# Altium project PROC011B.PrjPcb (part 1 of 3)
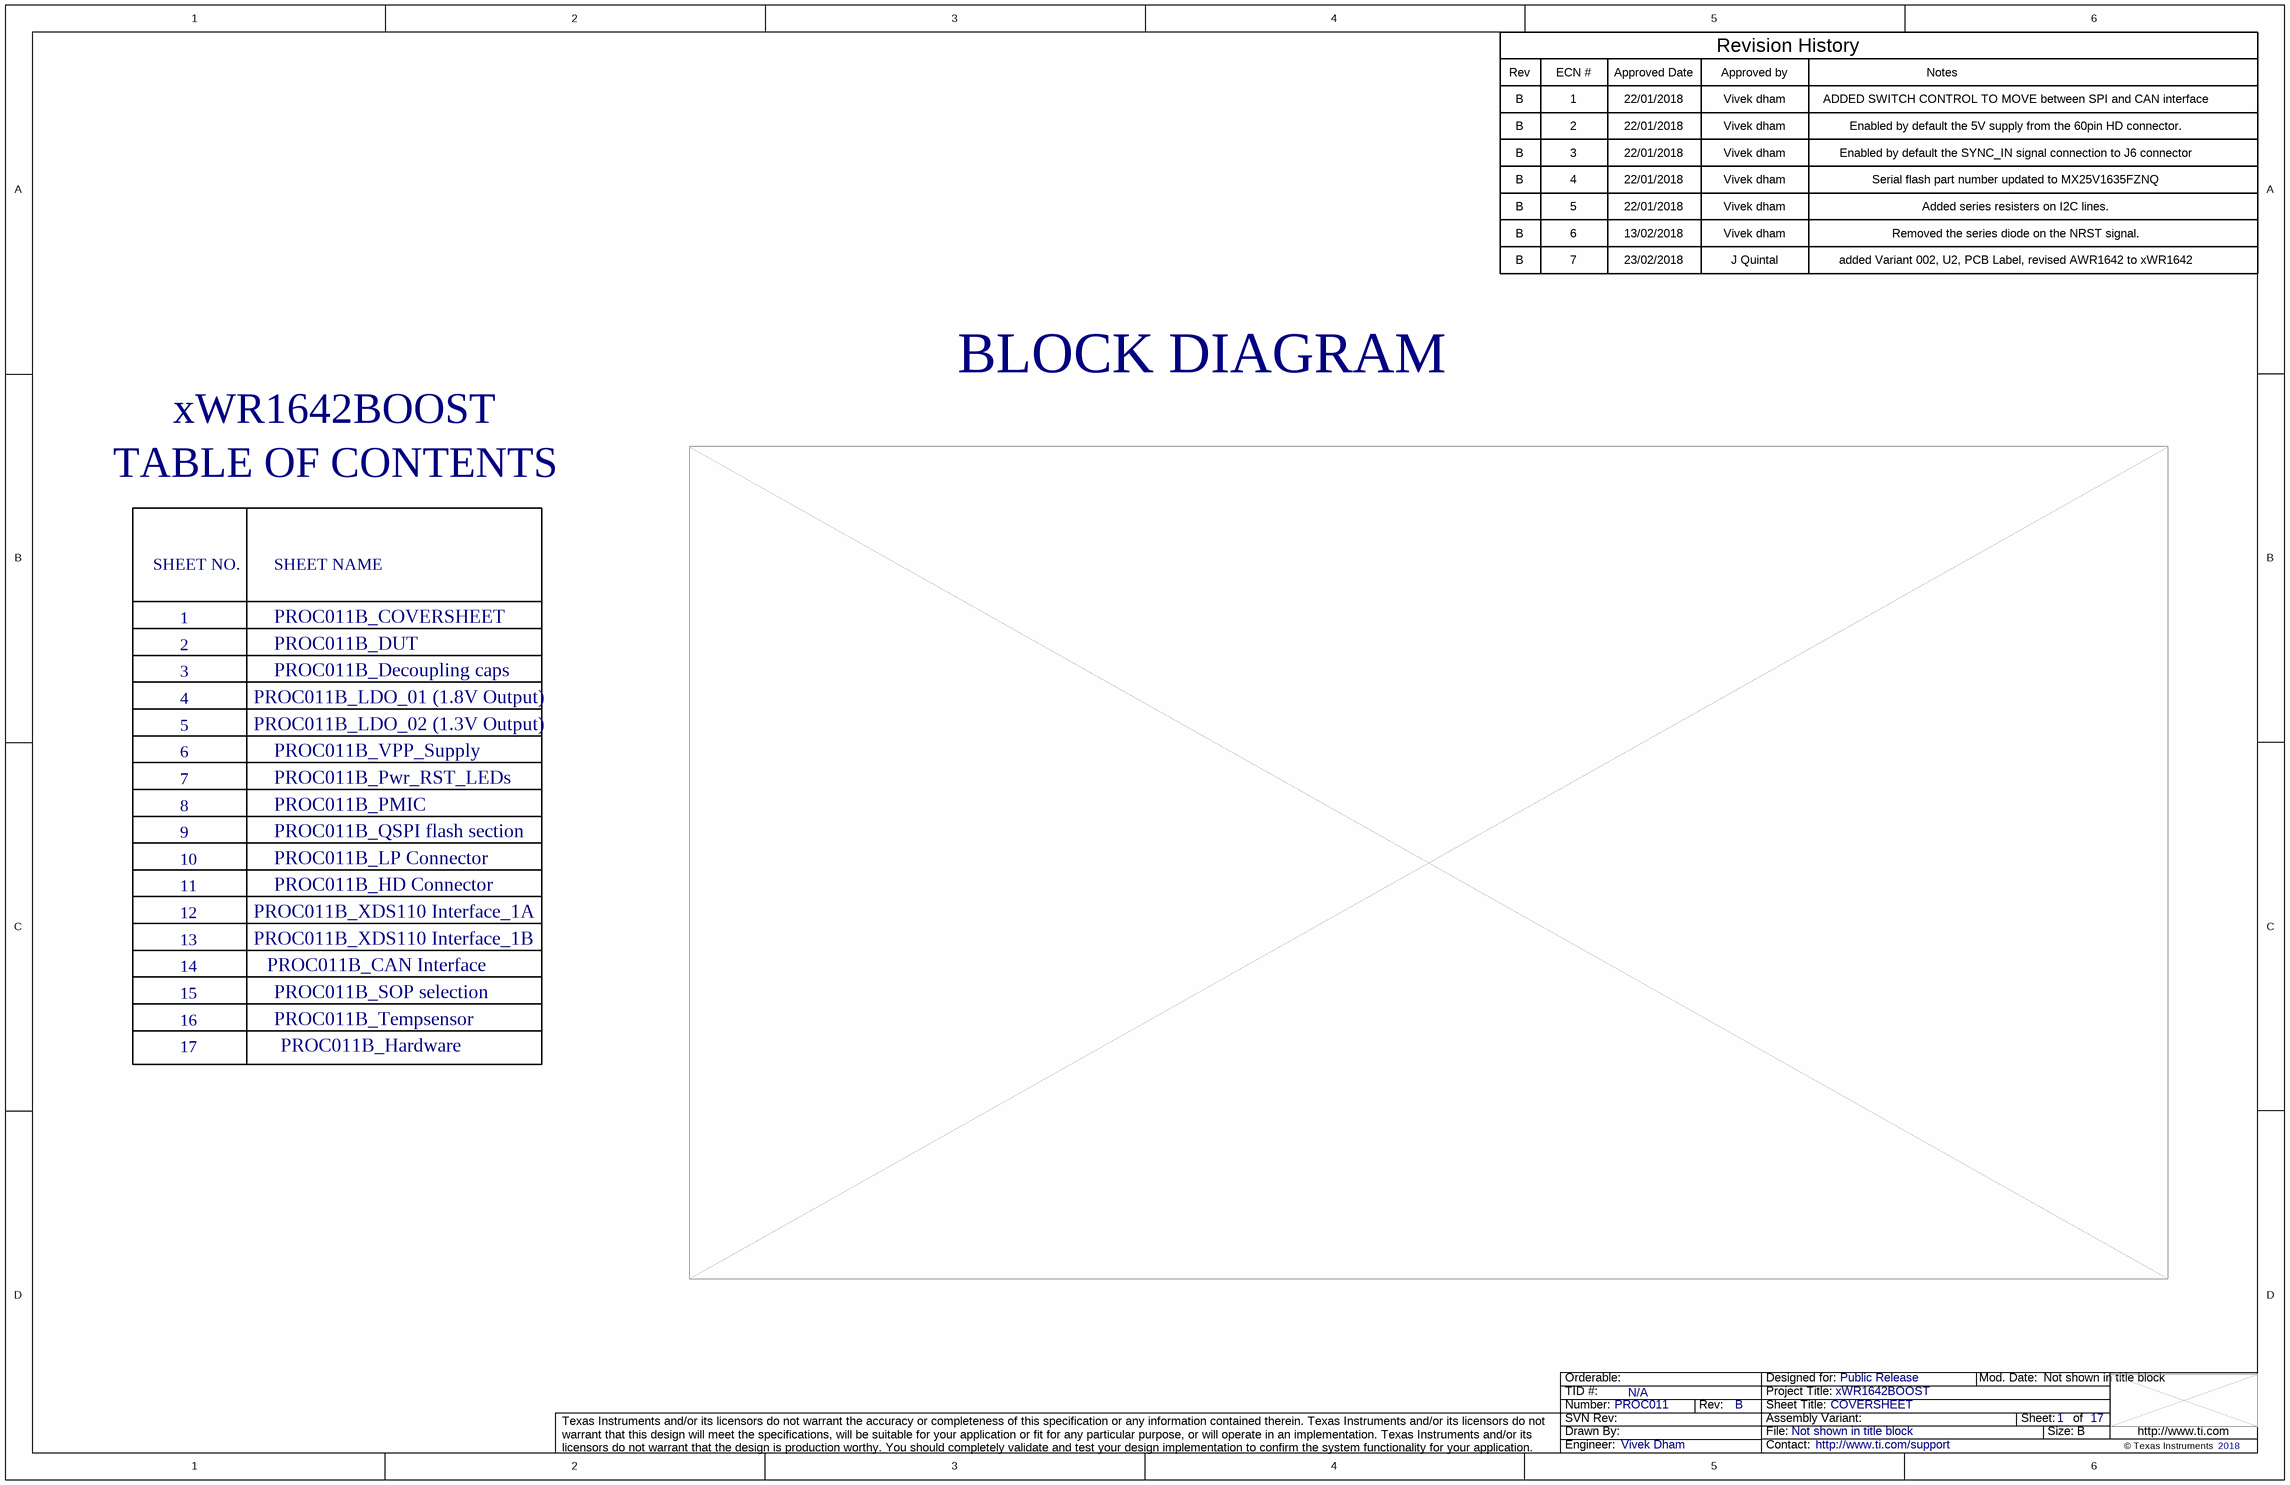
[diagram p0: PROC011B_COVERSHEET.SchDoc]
CopyrightYear: 2018; PCB_Layout: TESSOLVE; PCB_Rev: B; PRJ_Customer: Public Release; PRJ_Engineer: Vivek Dham; PRJ_Number: PROC011; PRJ_Title: xWR1642BOOST; SCH_Rev: B; TechSupport: http://www.ti.com/support; TID: N/A
17 sheets, 399 parts. Net scope: flat (ports and power ports of the same name join across sheets).
Board file: PROC011B_ASCII.PcbDoc
Sheets:
  PROC011B_COVERSHEET.SchDoc
  PROC011B_DUT.SchDoc
  PROC011B_Decoupling caps.SchDoc
  PROC011B_LDO_01 (1.8V Output).SchDoc
  PROC011B_LDO_02 (1.3V Output).SchDoc
  PROC011B_VPP_Supply.SchDoc
  PROC011B_Pwr_RST_LEDs.SchDoc
  PROC011B_PMIC.SchDoc
  PROC011B_QSPI flash section.SchDoc
  PROC011B_LP Connector.SchDoc
  PROC011B_HD Connector.SchDoc
  PROC011B_XDS110 Interface_1A.SchDoc
  PROC011B_XDS110 Interface_1B.SchDoc
  PROC011B_CAN Interface.SchDoc
  PROC011B_SOP selection.SchDoc
  PROC011B_Tempsensor.SchDoc
  PROC011B_Hardware.SchDoc

## Sheet PROC011B_COVERSHEET.SchDoc: COVERSHEET
size 431 x 279 mm; Date: Not shown in title block; ApprovedBy: Not shown in title block; CheckedBy: Not shown in title block; Author: Not shown in title block; CompanyName: Not shown in title block; Engineer: Not shown in title block; Organization: Not shown in title block; Address1: Not shown in title block; Address2: Not shown in title block; Address3: Not shown in title block; Address4: Not shown in title block; DocumentNumber: 1; Revision: Use project parameter SCH_Rev; SheetNumber: 1; SheetTotal: 17; PageSetup: Record=PageOptions¦CenterHorizontal=True¦CenterVertical=True¦PrintScale=0.64¦XCorrection=1.00¦YCorrection=1.00¦PrintKind=0¦BorderSize=5000000¦LeftOffset=0¦BottomOffset=0¦Orientation=2¦PaperLength=1000¦PaperWidth=1000¦Scale=100¦PaperSource=15¦PrintQuality=600¦MediaType=1¦DitherType=10¦PrintScaleMode=1¦PaperKind=Letter

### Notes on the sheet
- Rev
- B
- ECN #
- 1
- Approved Date
- 22/01/2018
- Approved by
- Vivek dham
- Revision History
- Notes
- ADDED SWITCH CONTROL TO MOVE between SPI and CAN interface
- 2
- 3
- Enabled by default the 5V supply from the 60pin HD connector.
- Enabled by default the SYNC_IN signal connection to J6 connector
- 4
- 5
- 6
- 13/02/2018
- Serial flash part number updated to MX25V1635FZNQ
- Added series resisters on I2C lines.
- Removed the series diode on the NRST signal.
- 7
- 23/02/2018
- J Quintal
- added Variant 002, U2, PCB Label, revised AWR1642 to xWR1642
- xWR1642BOOST
- BLOCK DIAGRAM
- TABLE OF CONTENTS
- SHEET NO.
- SHEET NAME
- PROC011B_COVERSHEET
- PROC011B_LDO_01 (1.8V Output)
- PROC011B_DUT
- PROC011B_Decoupling caps
- PROC011B_LDO_02 (1.3V Output)
- PROC011B_VPP_Supply
- 8
- 9
- PROC011B_Pwr_RST_LEDs
- PROC011B_PMIC
- PROC011B_QSPI flash section
- 10
- 11
- PROC011B_LP Connector
- PROC011B_HD Connector
- 12
- 13
- 14
- PROC011B_XDS110 Interface_1A
- PROC011B_XDS110 Interface_1B
- PROC011B_CAN Interface
- 15
- 16
- PROC011B_SOP selection
- PROC011B_Tempsensor
- 17
- PROC011B_Hardware

## Sheet PROC011B_DUT.SchDoc: DUT
size 431 x 279 mm; Date: Not shown in title block; ApprovedBy: Not shown in title block; CheckedBy: Not shown in title block; Author: Not shown in title block; CompanyName: Not shown in title block; Engineer: Not shown in title block; Organization: Not shown in title block; Address1: Not shown in title block; Address2: Not shown in title block; Address3: Not shown in title block; Address4: Not shown in title block; DocumentNumber: 1; Revision: Use project parameter SCH_Rev; SheetNumber: 2; SheetTotal: 17; PageSetup: Record=PageOptions¦CenterHorizontal=True¦CenterVertical=True¦PrintScale=0.64¦XCorrection=1.00¦YCorrection=1.00¦PrintKind=0¦BorderSize=5000000¦LeftOffset=0¦BottomOffset=0¦Orientation=2¦PaperLength=1000¦PaperWidth=1000¦Scale=100¦PaperSource=15¦PrintQuality=600¦MediaType=1¦DitherType=10¦PrintScaleMode=1¦PaperKind=Letter
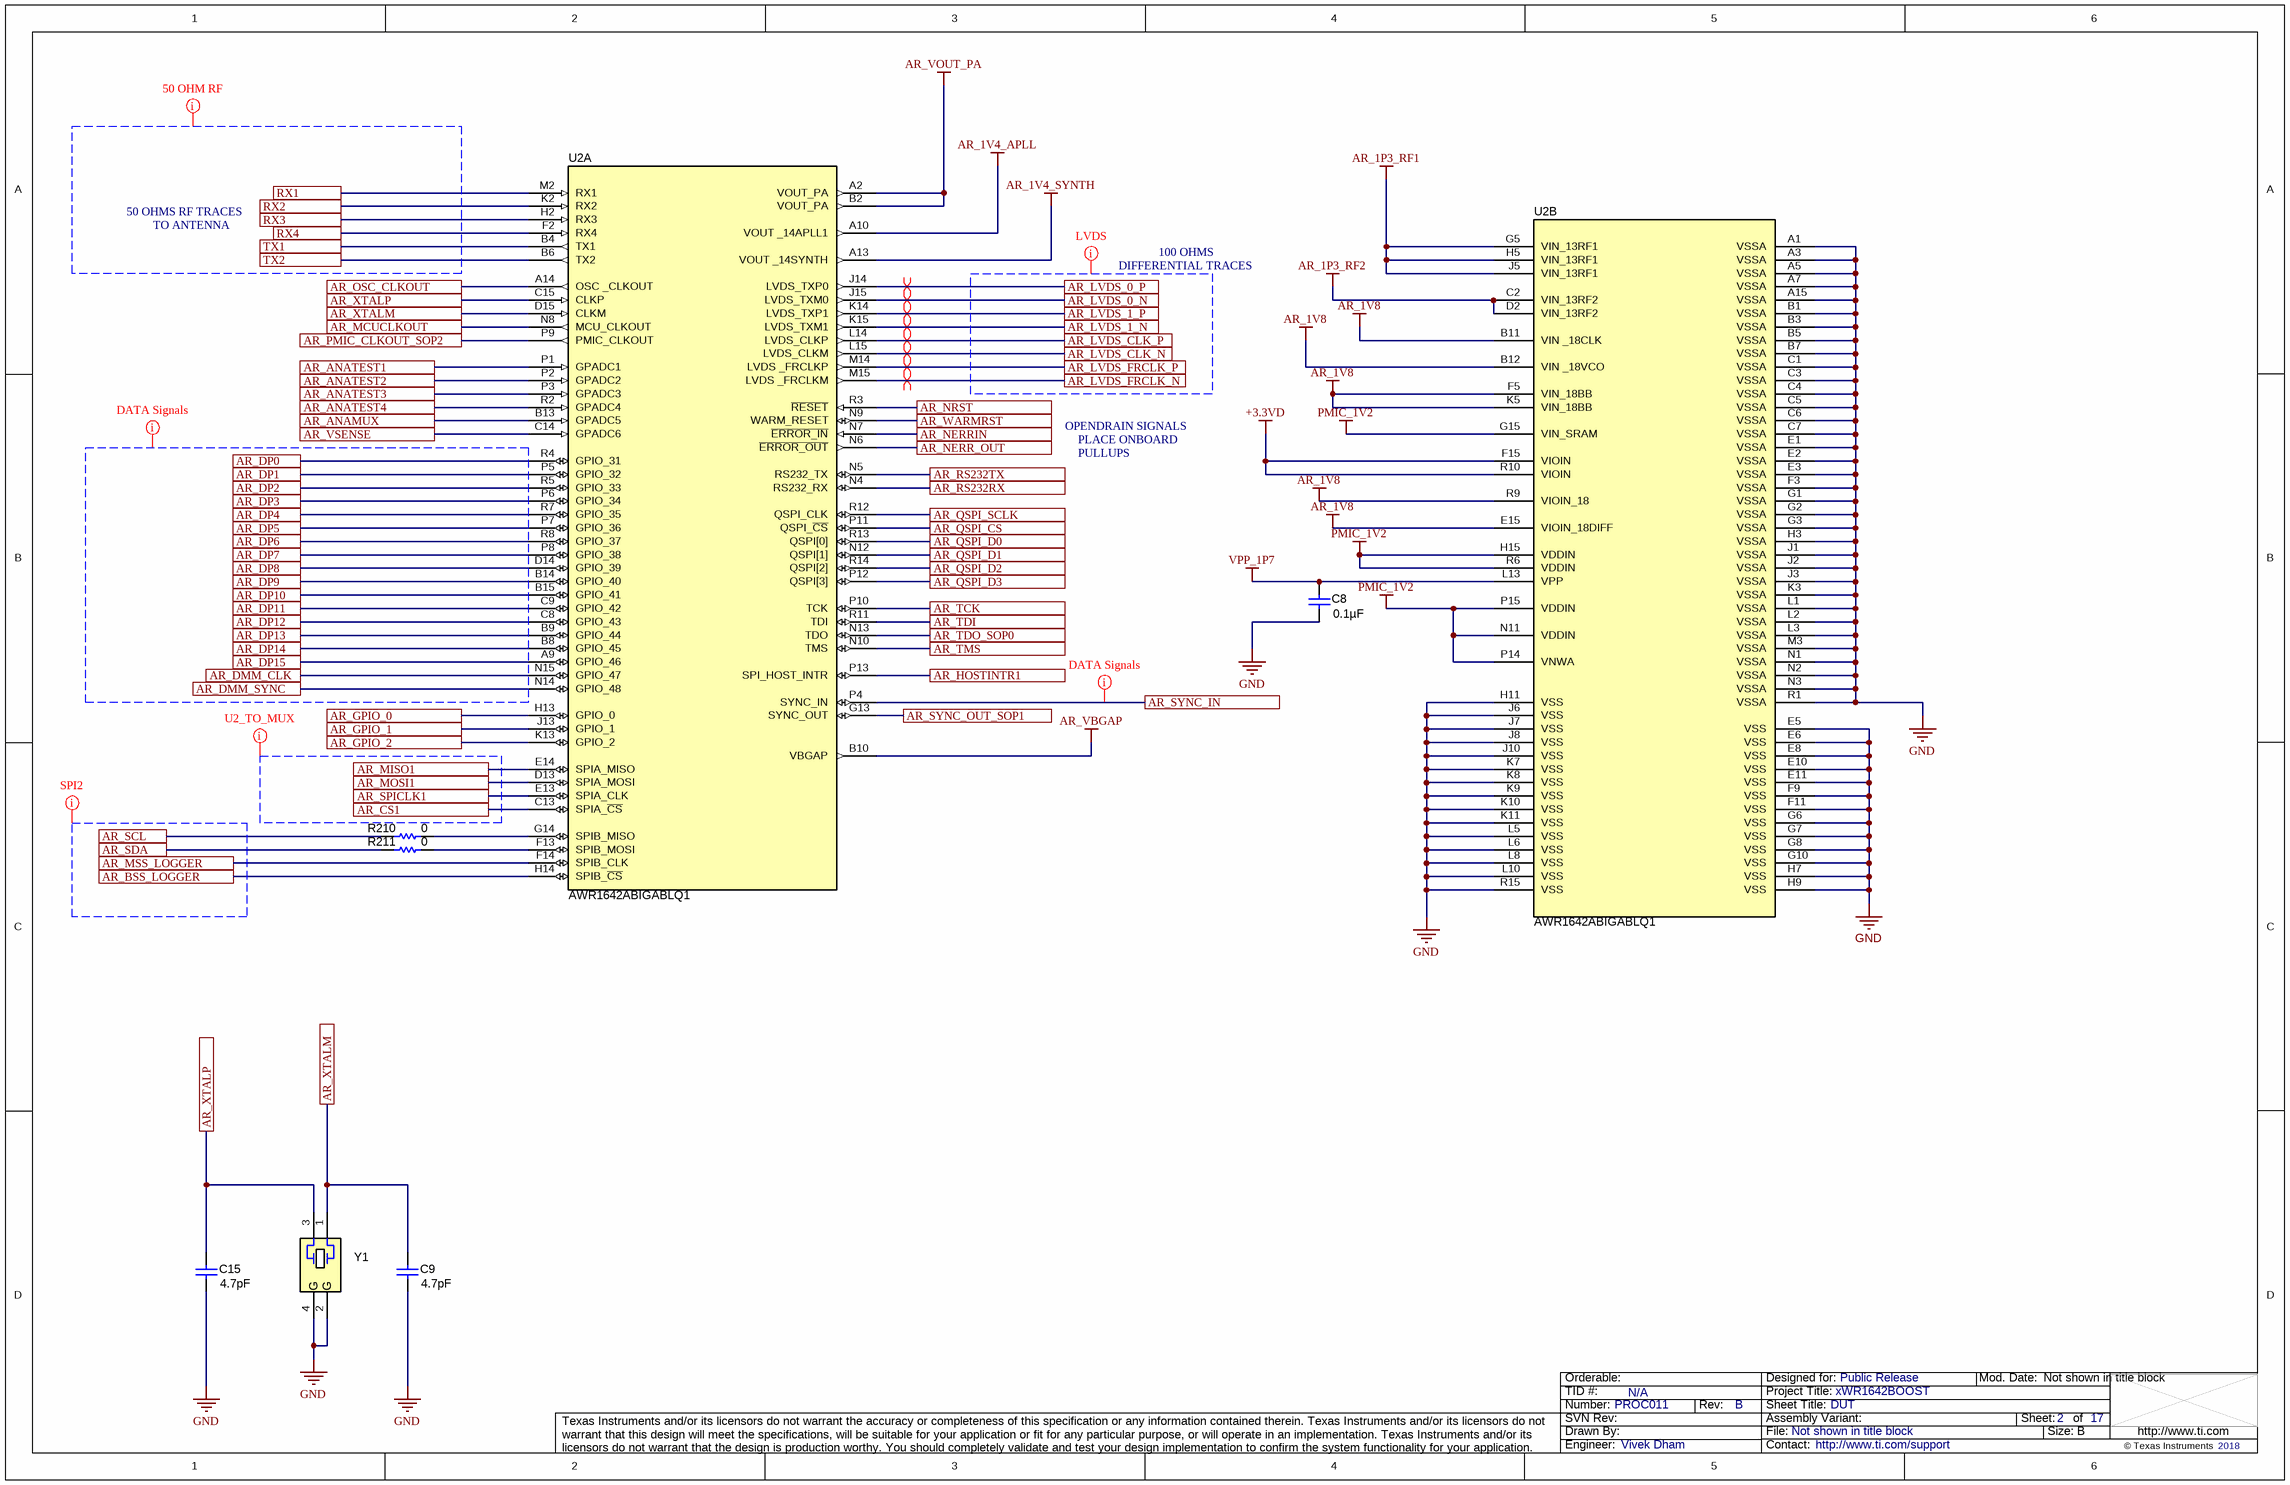
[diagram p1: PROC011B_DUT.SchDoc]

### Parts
C8  ValueDisplayed: 0.1µF  [0201_033]  (hidden comment: C0603X7S1A104K030BC)
C9  ValueDisplayed: 4.7pF  [0402L]  (hidden comment: GJM1555C1H4R7BB01D)
C15  ValueDisplayed: 4.7pF  [0402L]  (hidden comment: GJM1555C1H4R7BB01D)
R210  ValueDisplayed: 0  [0201]  (hidden comment: CRCW02010000Z0ED)
R211  ValueDisplayed: 0  [0201]  (hidden comment: CRCW02010000Z0ED)
U2  PartNumber: AWR1642ABIGABLQ1  [ABL0161B]  (hidden comment: X1642BIGABL)  (parts A,B of 2)
Y1  CX3225SA40000D0PTWCC  [Kyocera_CX3225SA]  (value not drawn)

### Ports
AR_ANAMUX, AR_ANATEST1, AR_ANATEST2, AR_ANATEST3, AR_ANATEST4, AR_BSS_LOGGER, AR_CS1, AR_DMM_CLK, AR_DMM_SYNC, AR_DP0, AR_DP1, AR_DP2, AR_DP3, AR_DP4, AR_DP5, AR_DP6, AR_DP7, AR_DP8, AR_DP9, AR_DP10, AR_DP11, AR_DP12, AR_DP13, AR_DP14, AR_DP15, AR_GPIO_0, AR_GPIO_1, AR_GPIO_2, AR_HOSTINTR1, AR_LVDS_0_N, AR_LVDS_0_P, AR_LVDS_1_N, AR_LVDS_1_P, AR_LVDS_CLK_N, AR_LVDS_CLK_P, AR_LVDS_FRCLK_N, AR_LVDS_FRCLK_P, AR_MCUCLKOUT, AR_MISO1, AR_MOSI1, AR_MSS_LOGGER, AR_NERR_OUT, AR_NERRIN, AR_NRST, AR_OSC_CLKOUT, AR_PMIC_CLKOUT_SOP2, AR_QSPI_CS, AR_QSPI_D0, AR_QSPI_D1, AR_QSPI_D2, AR_QSPI_D3, AR_QSPI_SCLK, AR_RS232RX, AR_RS232TX, AR_SCL, AR_SDA, AR_SPICLK1, AR_SYNC_IN, AR_SYNC_OUT_SOP1, AR_TCK, AR_TDI, AR_TDO_SOP0, AR_TMS, AR_VSENSE, AR_WARMRST, AR_XTALM, AR_XTALP, RX1, RX2, RX3, RX4, TX1, TX2

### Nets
+3.3VD: U2.F15(VIOIN) U2.R10(VIOIN)
AR_1P3_RF1: U2.G5(VIN_13RF1) U2.H5(VIN_13RF1) U2.J5(VIN_13RF1)
AR_1P3_RF2: U2.C2(VIN_13RF2) U2.D2(VIN_13RF2)
AR_1V4_APLL: U2.A10(VOUT__14APLL1)
AR_1V4_SYNTH: U2.A13(VOUT__14SYNTH)
AR_1V8: U2.B11(VIN__18CLK) U2.B12(VIN__18VCO) U2.E15(VIOIN_18DIFF) U2.F5(VIN_18BB) U2.K5(VIN_18BB) U2.R9(VIOIN_18)
AR_VBGAP: U2.B10(VBGAP)
AR_VOUT_PA: U2.A2(VOUT_PA) U2.B2(VOUT_PA)
GND: C8.1 C9.1 C15.1 U2.A1(VSSA) U2.A3(VSSA) U2.A5(VSSA) U2.A7(VSSA) U2.A15(VSSA) U2.B1(VSSA) U2.B3(VSSA) U2.B5(VSSA) U2.B7(VSSA) U2.C1(VSSA) U2.C3(VSSA) U2.C4(VSSA) U2.C5(VSSA) U2.C6(VSSA) U2.C7(VSSA) U2.E1(VSSA) U2.E2(VSSA) U2.E3(VSSA) U2.E5(VSS) U2.E6(VSS) U2.E8(VSS) U2.E10(VSS) U2.E11(VSS) U2.F3(VSSA) U2.F9(VSS) U2.F11(VSS) U2.G1(VSSA) U2.G2(VSSA) U2.G3(VSSA) U2.G6(VSS) U2.G7(VSS) U2.G8(VSS) U2.G10(VSS) U2.H3(VSSA) U2.H7(VSS) U2.H9(VSS) U2.H11(VSS) U2.J1(VSSA) U2.J2(VSSA) U2.J3(VSSA) U2.J6(VSS) U2.J7(VSS) U2.J8(VSS) U2.J10(VSS) U2.K3(VSSA) U2.K7(VSS) U2.K8(VSS) U2.K9(VSS) U2.K10(VSS) U2.K11(VSS) U2.L1(VSSA) U2.L2(VSSA) U2.L3(VSSA) U2.L5(VSS) U2.L6(VSS) U2.L8(VSS) U2.L10(VSS) U2.M3(VSSA) U2.N1(VSSA) U2.N2(VSSA) U2.N3(VSSA) U2.R1(VSSA) U2.R15(VSS) Y1.2(GND) Y1.4(GND)
PMIC_1V2: U2.G15(VIN_SRAM) U2.H15(VDDIN) U2.N11(VDDIN) U2.P14(VNWA) U2.P15(VDDIN) U2.R6(VDDIN)
VPP_1P7: C8.2 U2.L13(VPP)
AR_ANAMUX: U2.B13(GPADC5) ; port AR_ANAMUX
AR_ANATEST1: U2.P1(GPADC1) ; port AR_ANATEST1
AR_ANATEST2: U2.P2(GPADC2) ; port AR_ANATEST2
AR_ANATEST3: U2.P3(GPADC3) ; port AR_ANATEST3
AR_ANATEST4: U2.R2(GPADC4) ; port AR_ANATEST4
AR_BSS_LOGGER: U2.H14(SPIB_~{CS}) ; port AR_BSS_LOGGER
AR_CS1: U2.C13(SPIA_~{CS}) ; port AR_CS1
AR_DMM_CLK: U2.N15(GPIO_47) ; port AR_DMM_CLK
AR_DMM_SYNC: U2.N14(GPIO_48) ; port AR_DMM_SYNC
AR_DP0: U2.R4(GPIO_31) ; port AR_DP0
AR_DP1: U2.P5(GPIO_32) ; port AR_DP1
AR_DP2: U2.R5(GPIO_33) ; port AR_DP2
AR_DP3: U2.P6(GPIO_34) ; port AR_DP3
AR_DP4: U2.R7(GPIO_35) ; port AR_DP4
AR_DP5: U2.P7(GPIO_36) ; port AR_DP5
AR_DP6: U2.R8(GPIO_37) ; port AR_DP6
AR_DP7: U2.P8(GPIO_38) ; port AR_DP7
AR_DP8: U2.D14(GPIO_39) ; port AR_DP8
AR_DP9: U2.B14(GPIO_40) ; port AR_DP9
AR_DP10: U2.B15(GPIO_41) ; port AR_DP10
AR_DP11: U2.C9(GPIO_42) ; port AR_DP11
AR_DP12: U2.C8(GPIO_43) ; port AR_DP12
AR_DP13: U2.B9(GPIO_44) ; port AR_DP13
AR_DP14: U2.B8(GPIO_45) ; port AR_DP14
AR_DP15: U2.A9(GPIO_46) ; port AR_DP15
AR_GPIO_0: U2.H13(GPIO_0) ; port AR_GPIO_0
AR_GPIO_1: U2.J13(GPIO_1) ; port AR_GPIO_1
AR_GPIO_2: U2.K13(GPIO_2) ; port AR_GPIO_2
AR_HOSTINTR1: U2.P13(SPI_HOST_INTR) ; port AR_HOSTINTR1
AR_LVDS_0_N: U2.J15(LVDS_TXM0) ; port AR_LVDS_0_N
AR_LVDS_0_P: U2.J14(LVDS_TXP0) ; port AR_LVDS_0_P
AR_LVDS_1_N: U2.K15(LVDS_TXM1) ; port AR_LVDS_1_N
AR_LVDS_1_P: U2.K14(LVDS_TXP1) ; port AR_LVDS_1_P
AR_LVDS_CLK_N: U2.L15(LVDS_CLKM) ; port AR_LVDS_CLK_N
AR_LVDS_CLK_P: U2.L14(LVDS_CLKP) ; port AR_LVDS_CLK_P
AR_LVDS_FRCLK_N: U2.M15(LVDS__FRCLKM) ; port AR_LVDS_FRCLK_N
AR_LVDS_FRCLK_P: U2.M14(LVDS__FRCLKP) ; port AR_LVDS_FRCLK_P
AR_MCUCLKOUT: U2.N8(MCU_CLKOUT) ; port AR_MCUCLKOUT
AR_MISO1: U2.E14(SPIA_MISO) ; port AR_MISO1
AR_MOSI1: U2.D13(SPIA_MOSI) ; port AR_MOSI1
AR_MSS_LOGGER: U2.F14(SPIB_CLK) ; port AR_MSS_LOGGER
AR_NERR_OUT: U2.N6(~{ERROR_OUT}) ; port AR_NERR_OUT
AR_NERRIN: U2.N7(~{ERROR_IN}) ; port AR_NERRIN
AR_NRST: U2.R3(~{RESET}) ; port AR_NRST
AR_OSC_CLKOUT: U2.A14(OSC__CLKOUT) ; port AR_OSC_CLKOUT
AR_PMIC_CLKOUT_SOP2: U2.P9(PMIC_CLKOUT) ; port AR_PMIC_CLKOUT_SOP2
AR_QSPI_CS: U2.P11(QSPI_~{CS}) ; port AR_QSPI_CS
AR_QSPI_D0: U2.R13(QSPI[0]) ; port AR_QSPI_D0
AR_QSPI_D1: U2.N12(QSPI[1]) ; port AR_QSPI_D1
AR_QSPI_D2: U2.R14(QSPI[2]) ; port AR_QSPI_D2
AR_QSPI_D3: U2.P12(QSPI[3]) ; port AR_QSPI_D3
AR_QSPI_SCLK: U2.R12(QSPI_CLK) ; port AR_QSPI_SCLK
AR_RS232RX: U2.N4(RS232_RX) ; port AR_RS232RX
AR_RS232TX: U2.N5(RS232_TX) ; port AR_RS232TX
AR_SCL: R210.1 ; port AR_SCL
AR_SDA: R211.1 ; port AR_SDA
AR_SPICLK1: U2.E13(SPIA_CLK) ; port AR_SPICLK1
AR_SYNC_IN: U2.P4(SYNC_IN) ; port AR_SYNC_IN
AR_SYNC_OUT_SOP1: U2.G13(SYNC_OUT) ; port AR_SYNC_OUT_SOP1
AR_TCK: U2.P10(TCK) ; port AR_TCK
AR_TDI: U2.R11(TDI) ; port AR_TDI
AR_TDO_SOP0: U2.N13(TDO) ; port AR_TDO_SOP0
AR_TMS: U2.N10(TMS) ; port AR_TMS
AR_VSENSE: U2.C14(GPADC6) ; port AR_VSENSE
AR_WARMRST: U2.N9(WARM_RESET) ; port AR_WARMRST
AR_XTALM: C9.2 U2.D15(CLKM) Y1.1 ; port AR_XTALM
AR_XTALP: C15.2 U2.C15(CLKP) Y1.3 ; port AR_XTALP
RX1: U2.M2(RX1) ; port RX1
RX2: U2.K2(RX2) ; port RX2
RX3: U2.H2(RX3) ; port RX3
RX4: U2.F2(RX4) ; port RX4
TX1: U2.B4(TX1) ; port TX1
TX2: U2.B6(TX2) ; port TX2
NetR210_2: R210.2 U2.G14(SPIB_MISO)
NetR211_2: R211.2 U2.F13(SPIB_MOSI)

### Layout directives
differential pair: AR_LVDS_0_N, AR_LVDS_0_P, AR_LVDS_1_N, AR_LVDS_1_P, AR_LVDS_CLK_N, AR_LVDS_CLK_P, AR_LVDS_FRCLK_N, AR_LVDS_FRCLK_P
net class LVDS: (no net found under the mark)
net class DATA0-15: (no net found under the mark), AR_SYNC_IN
net class RF_RX&TX: (no net found under the mark)
net class SPI2: (no net found under the mark)
net class U2_TO_MUX: (no net found under the mark)

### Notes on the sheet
- 50 OHMS RF TRACES
- TO ANTENNA
- DIFFERENTIAL TRACES
- 100 OHMS
- OPENDRAIN SIGNALS
- PLACE ONBOARD
- PULLUPS

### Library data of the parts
C8 = CMP-0078219-1: CAP, CERM, 0.1 µF, 10 V,+/- 10%, X7S, 0201; Manufacturer: TDK; TaMin_C: -55°C; Polarized: N; Green_Lifecycle: NRND; SizeAreaWB_mm2: 2.08; Green_REACh: Passed; U/M: EA; Value: 0.1uF; TaMax_C: 125°C; SizeZ_mm: 0.33; SizeX_mm: 0.6; SizeY_mm: 0.3; Cap_Case: 0201; Value2: 10V; SizeArea_mm2: 0.18; CompType: Capacitor; Cap_F: 100nF; AEC Category: Q200
C9 C15 = CMP-0006367-2: CAP, CERM, 4.7 pF, 50 V, +/- 2%, C0G/NP0, 0402; Manufacturer: MuRata; TaMin_C: -55°C; Polarized: N; SizeAreaWB_mm2: 3; Value1: Unknown; U/M: EA; Value: 4.7pF; TaMax_C: 125°C; SizeZ_mm: 0.6; SizeX_mm: 1; SizeY_mm: 0.5; Cap_Case: 0402; Value2: 50V; CompType: Capacitor; AEC Category: Q200
R210 R211 = CMP-0027008-4: RES, 0, 5%, 0.05 W, 0201; Manufacturer: Vishay-Dale; Power_W: 50mW; TempCo: ppm/C; Value_Code: 0000; Value: 0; EIA_Code: E24; SizeX_mm: 0.6; SizeY_mm: 0.3; SizeZ_mm: 0.26; Value2: 0.05W; SizeArea_mm2: 0.18; CompType: Resistor; AEC Qualified: N; AEC Category: Q200; INSTALL: DNP
U2 = CMP-0077311-2: Single-Chip 77- and 79-GHz FMCW Radar Sensor, ABL0161B (FCBGA-161); Manufacturer: Texas Instruments; SizeX_mm: 10.4; CompType: IC; SizeZ_mm: 1.17; SizeArea_mm2: 108.16; SizeAreaWB_mm2: 153.76; U/M: EA
Y1 = CMP-0004694-3: Crystal, 40 MHz, 8pF, SMD; Manufacturer: Kyocera; TaMin_C: -40°C; Frequency Stability: +/-200ppm; SizeAreaWB_mm2: 14.7; Frequency_Fixed: 40MHz; TaMax_C: 125°C; SizeZ_mm: 0.8; SizeX_mm: 2.5; SizeY_mm: 3.2; SizeArea_mm2: 8

## Sheet PROC011B_Decoupling caps.SchDoc: Decoupling caps
size 431 x 279 mm; Date: Not shown in title block; ApprovedBy: Not shown in title block; CheckedBy: Not shown in title block; Author: Not shown in title block; CompanyName: Not shown in title block; Engineer: Not shown in title block; Organization: Not shown in title block; Address1: Not shown in title block; Address2: Not shown in title block; Address3: Not shown in title block; Address4: Not shown in title block; DocumentNumber: 1; Revision: Use project parameter SCH_Rev; SheetNumber: 3; SheetTotal: 17; PageSetup: Record=PageOptions¦CenterHorizontal=True¦CenterVertical=True¦PrintScale=1.00¦XCorrection=1.00¦YCorrection=1.00¦PrintKind=0¦BorderSize=5000000¦LeftOffset=0¦BottomOffset=0¦Orientation=2¦PaperLength=1000¦PaperWidth=1000¦Scale=100¦PaperSource=15¦PrintQuality=600¦MediaType=1¦DitherType=10¦PaperKind=Letter¦PrintScaleMode=1
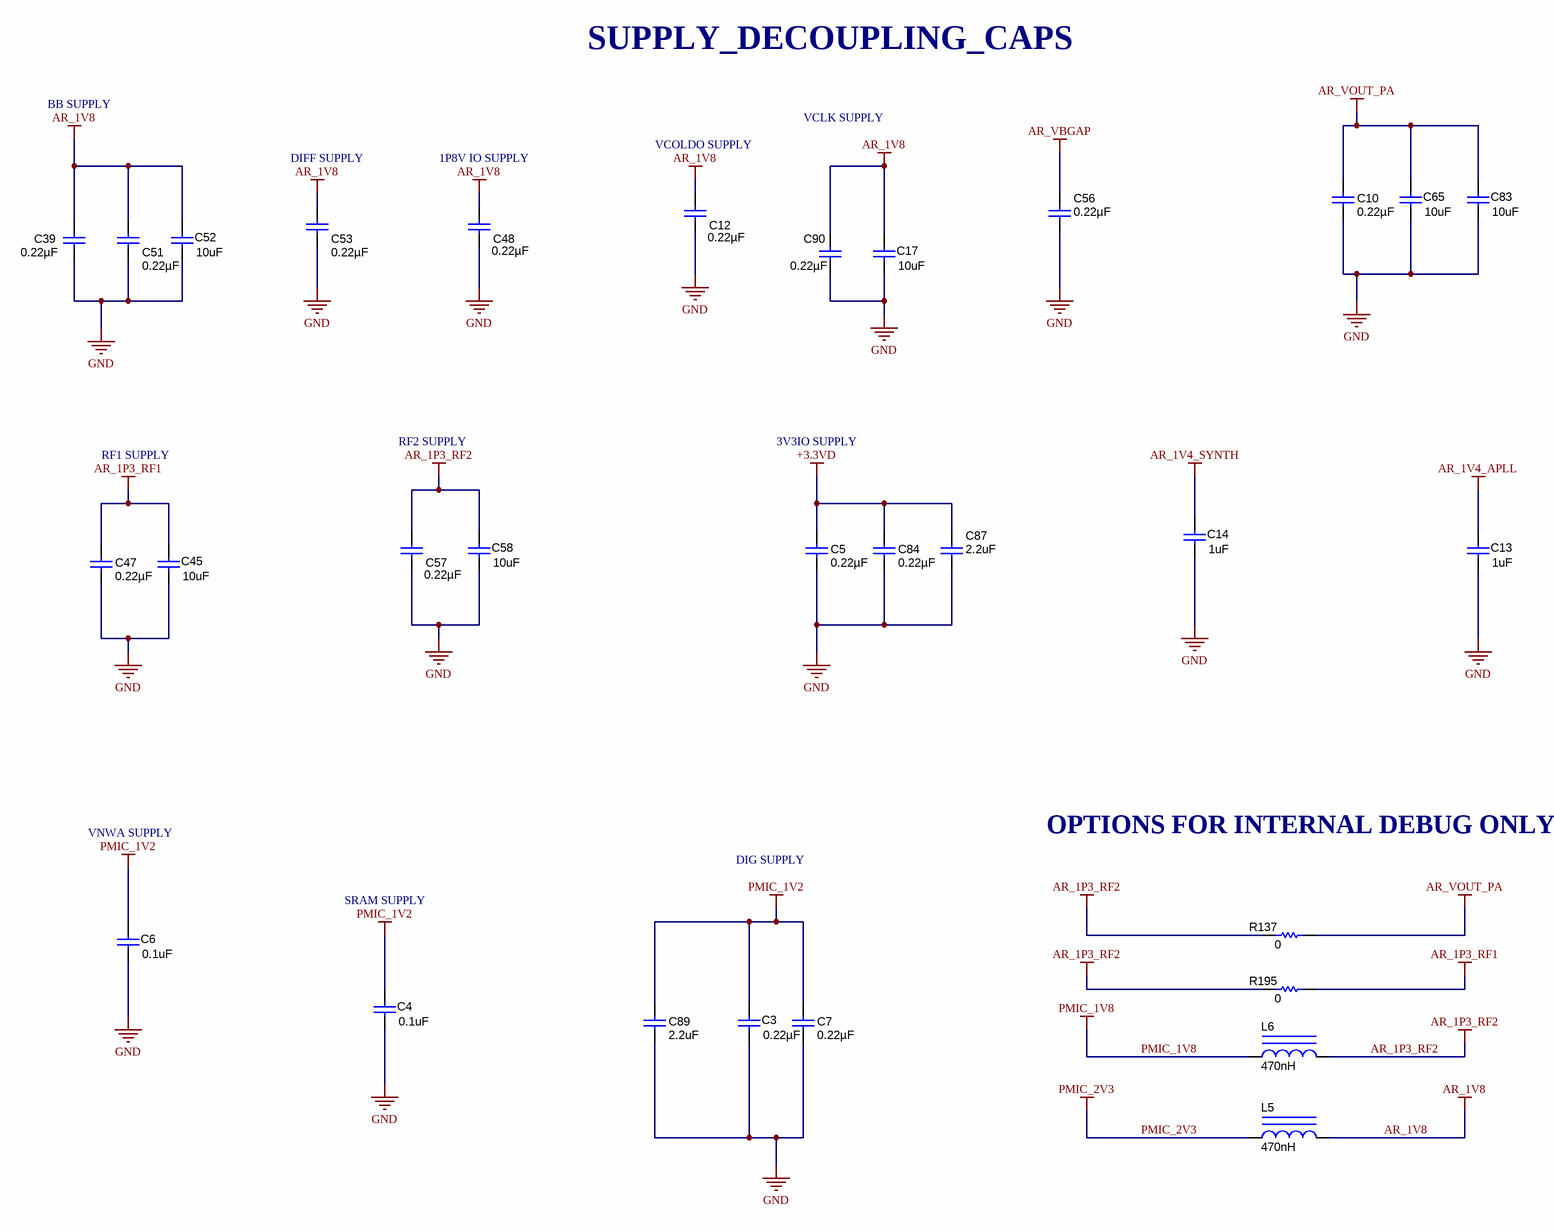
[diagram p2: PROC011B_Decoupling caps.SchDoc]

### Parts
C3  ValueDisplayed: 0.22µF  [0402L]  (hidden comment: GCM155R71C224KE02D)
C4  ValueDisplayed: 0.1uF  [0402L]  (hidden comment: GCM155R71C104KA55D)
C5  ValueDisplayed: 0.22µF  [0402L]  (hidden comment: GCM155R71C224KE02D)
C6  ValueDisplayed: 0.1uF  [0402L]  (hidden comment: GCM155R71C104KA55D)
C7  ValueDisplayed: 0.22µF  [0402L]  (hidden comment: GCM155R71C224KE02D)
C10  ValueDisplayed: 0.22µF  [0402L]  (hidden comment: GCM155R71C224KE02D)
C12  ValueDisplayed: 0.22µF  [0402L]  (hidden comment: GCM155R71C224KE02D)
C13  ValueDisplayed: 1uF  [0603]  (hidden comment: GCM188R71C105KA64D)
C14  ValueDisplayed: 1uF  [0603]  (hidden comment: GCM188R71C105KA64D)
C17  ValueDisplayed: 10uF  [0805_HV]  (hidden comment: GCM21BR71A106KE22L)
C39  ValueDisplayed: 0.22µF  [0402L]  (hidden comment: GCM155R71C224KE02D)
C45  ValueDisplayed: 10uF  [0805_HV]  (hidden comment: GCM21BR71A106KE22L)
C47  ValueDisplayed: 0.22µF  [0402L]  (hidden comment: GCM155R71C224KE02D)
C48  ValueDisplayed: 0.22µF  [0402L]  (hidden comment: GCM155R71C224KE02D)
C51  ValueDisplayed: 0.22µF  [0402L]  (hidden comment: GCM155R71C224KE02D)
C52  ValueDisplayed: 10uF  [0805_HV]  (hidden comment: GCM21BR71A106KE22L)
C53  ValueDisplayed: 0.22µF  [0402L]  (hidden comment: GCM155R71C224KE02D)
C56  ValueDisplayed: 0.22µF  [0402L]  (hidden comment: GCM155R71C224KE02D)
C57  ValueDisplayed: 0.22µF  [0402L]  (hidden comment: GCM155R71C224KE02D)
C58  ValueDisplayed: 10uF  [0805_HV]  (hidden comment: GCM21BR71A106KE22L)
C65  ValueDisplayed: 10uF  [0805_HV]  (hidden comment: GCM21BR71A106KE22L)
C83  ValueDisplayed: 10uF  [0805_HV]  (hidden comment: GCM21BR71A106KE22L)
C84  ValueDisplayed: 0.22µF  [0402L]  (hidden comment: GCM155R71C224KE02D)
C87  ValueDisplayed: 2.2uF  [0603]  (hidden comment: GCM188R70J225KE22D)
C89  ValueDisplayed: 2.2uF  [0603]  (hidden comment: GCM188R70J225KE22D)
C90  ValueDisplayed: 0.22µF  [0402L]  (hidden comment: GCM155R71C224KE02D)
L5  ValueDisplayed: 470nH  [DFE252012P]  (hidden comment: DFE252012P-R47M=P2)
L6  ValueDisplayed: 470nH  [DFE252012P]  (hidden comment: DFE252012P-R47M=P2)
R137  ValueDisplayed: 0  [0603]  (hidden comment: MCT06030Z0000ZP500)
R195  ValueDisplayed: 0  [0603]  (hidden comment: MCT06030Z0000ZP500)

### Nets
+3.3VD: C5.2 C84.2 C87.2
AR_1P3_RF1: C45.2 C47.2 R195.2
AR_1P3_RF2: C57.2 C58.2 L6.2 R137.1 R195.1
AR_1V4_APLL: C13.2
AR_1V4_SYNTH: C14.2
AR_1V8: C12.2 C17.2 C39.2 C48.2 C51.2 C52.2 C53.2 C90.2 L5.2
AR_VBGAP: C56.2
AR_VOUT_PA: C10.2 C65.2 C83.2 R137.2
GND: C3.1 C4.1 C5.1 C6.1 C7.1 C10.1 C12.1 C13.1 C14.1 C17.1 C39.1 C45.1 C47.1 C48.1 C51.1 C52.1 C53.1 C56.1 C57.1 C58.1 C65.1 C83.1 C84.1 C87.1 C89.1 C90.1
PMIC_1V2: C3.2 C4.2 C6.2 C7.2 C89.2
PMIC_1V8: L6.1
PMIC_2V3: L5.1

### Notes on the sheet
- SUPPLY_DECOUPLING_CAPS
- BB SUPPLY
- DIFF SUPPLY
- 1P8V IO SUPPLY
- VCOLDO SUPPLY
- VCLK SUPPLY
- RF1 SUPPLY
- RF2 SUPPLY
- 3V3IO SUPPLY
- VNWA SUPPLY
- OPTIONS FOR INTERNAL DEBUG ONLY
- SRAM SUPPLY
- DIG SUPPLY

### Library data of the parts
C3 C5 C7 C10 C12 C39 C47 C48 C51 C53 C56 C57 C84 C90 = CMP-0078265-1: CAP, CERM, 0.22 µF, 16 V,+/- 10%, X7R, AEC-Q200 Grade 1, 0402; Manufacturer: MuRata; TaMin_C: -55°C; Polarized: N; SizeAreaWB_mm2: 3; U/M: EA; Value: 0.22uF; TaMax_C: 125°C; SizeZ_mm: 0.6; SizeX_mm: 1; SizeY_mm: 0.5; Cap_Case: 0402; Value2: 16V; CompType: Capacitor; AEC Qualified: Y; Cap_F: 220nF; AEC Category: Q200
C4 C6 = CMP-0006351-2: CAP, CERM, 0.1 uF, 16 V, +/- 10%, X7R, 0402; Manufacturer: MuRata; TaMin_C: -55°C; Polarized: N; SizeAreaWB_mm2: 3; Value1: Unknown; U/M: EA; Value: 0.1uF; TaMax_C: 125°C; SizeZ_mm: 0.6; SizeX_mm: 1; SizeY_mm: 0.5; Cap_Case: 0402; Value2: 16V; Cap_F: 100nF; AEC Category: Q200
C13 C14 = CMP-0007136-5: CAP, CERM, 1 uF, 16 V, +/- 10%, X7R, AEC-Q200 Grade 1, 0603; Manufacturer: MuRata; TaMin_C: -55°C; Polarized: N; SizeAreaWB_mm2: 4.68; Value1: Unknown; U/M: EA; Value: 1uF; TaMax_C: 125°C; SizeZ_mm: 1; SizeX_mm: 1.6; SizeY_mm: 0.8; Value2: 16V; SizeArea_mm2: 1.28; AEC Qualified: Y; Cap_F: 1µF; AEC Category: Q200
C17 C45 C52 C58 C65 = CMP-0008017-2: CAP, CERM, 10 uF, 10 V, +/- 10%, X7R, 0805; Manufacturer: MuRata; TaMin_C: -55°C; Polarized: N; SizeAreaWB_mm2: 6.75; Value1: Unknown; U/M: EA; Value: 10uF; TaMax_C: 125°C; SizeZ_mm: 1.45; SizeX_mm: 2; SizeY_mm: 1.25; Cap_Case: 0805; Value2: 10V; SizeArea_mm2: 2.5; CompType: Capacitor; Cap_F: 10µF; AEC Category: Q200
C83 = CMP-0008017-2: CAP, CERM, 10 uF, 10 V, +/- 10%, X7R, 0805; Manufacturer: MuRata; TaMin_C: -55°C; Polarized: N; SizeAreaWB_mm2: 6.75; Value1: Unknown; U/M: EA; Value: 10uF; TaMax_C: 125°C; SizeZ_mm: 1.45; SizeX_mm: 2; SizeY_mm: 1.25; Cap_Case: 0805; Value2: 10V; SizeArea_mm2: 2.5; CompType: Capacitor; Cap_F: 10µF; AEC Category: Q200; INSTYALATION: DNP
C87 C89 = CMP-0007134-5: CAP, CERM, 2.2 uF, 6.3 V, +/- 10%, X7R, AEC-Q200 Grade 1, 0603; Manufacturer: MuRata; TaMin_C: -55°C; Polarized: N; SizeAreaWB_mm2: 4.68; Value1: Unknown; U/M: EA; Value: 2.2uF; TaMax_C: 125°C; SizeZ_mm: 1; SizeX_mm: 1.6; SizeY_mm: 0.8; Value2: 6.3V; SizeArea_mm2: 1.28; AEC Qualified: Y; Cap_F: 2.2µF; AEC Category: Q200
L5 L6 = CMP-0058946-1: Inductor, Shielded, 470 nH, 4.7 A, 0.021 ohm, SMD; Manufacturer: MuRata Toko; Isat: 6.4A @ 30% inductance drop; Irms: 4.7A @ 40C rise; SizeAreaWB_mm2: 10.5; DCR_ohm: 0.021; Value: 470nH; Imax_A: 4.7A; SizeZ_mm: 1.2; SizeX_mm: 2.5; SizeY_mm: 2; SizeArea_mm2: 5; AEC Category: Q200; INSTALATION: DNP
R137 R195 = CMP-0025884-3: RES, 0, 5%, 0.125 W, 0603; Manufacturer: Vishay/Beyschlag; Power_W: 125mW; TempCo: ppm/C; Value_Code: 0000; U/M: EA; Value: 0; EIA_Code: E24; SizeX_mm: 1.6; SizeY_mm: 0.8; SizeZ_mm: 1; Value2: 0.125W; SizeArea_mm2: 1.28; CompType: Resistor; AEC Qualified: N; AEC Category: Q200; INSTALATION: DNP

## Sheet PROC011B_LDO_01 (1.8V Output).SchDoc: LDO_01 (1.8V Output)
size 431 x 279 mm; Date: Not shown in title block; ApprovedBy: Not shown in title block; CheckedBy: Not shown in title block; Author: Not shown in title block; CompanyName: Not shown in title block; Engineer: Not shown in title block; Organization: Not shown in title block; Address1: Not shown in title block; Address2: Not shown in title block; Address3: Not shown in title block; Address4: Not shown in title block; DocumentNumber: 1; Revision: Use project parameter SCH_Rev; SheetNumber: 4; SheetTotal: 17; PageSetup: Record=PageOptions¦CenterHorizontal=True¦CenterVertical=True¦PrintScale=1.00¦XCorrection=1.00¦YCorrection=1.00¦PrintKind=0¦BorderSize=5000000¦LeftOffset=0¦BottomOffset=0¦Orientation=2¦PaperLength=1000¦PaperWidth=1000¦Scale=100¦PaperSource=15¦PrintQuality=600¦MediaType=1¦DitherType=10¦PaperKind=Letter¦PrintScaleMode=1
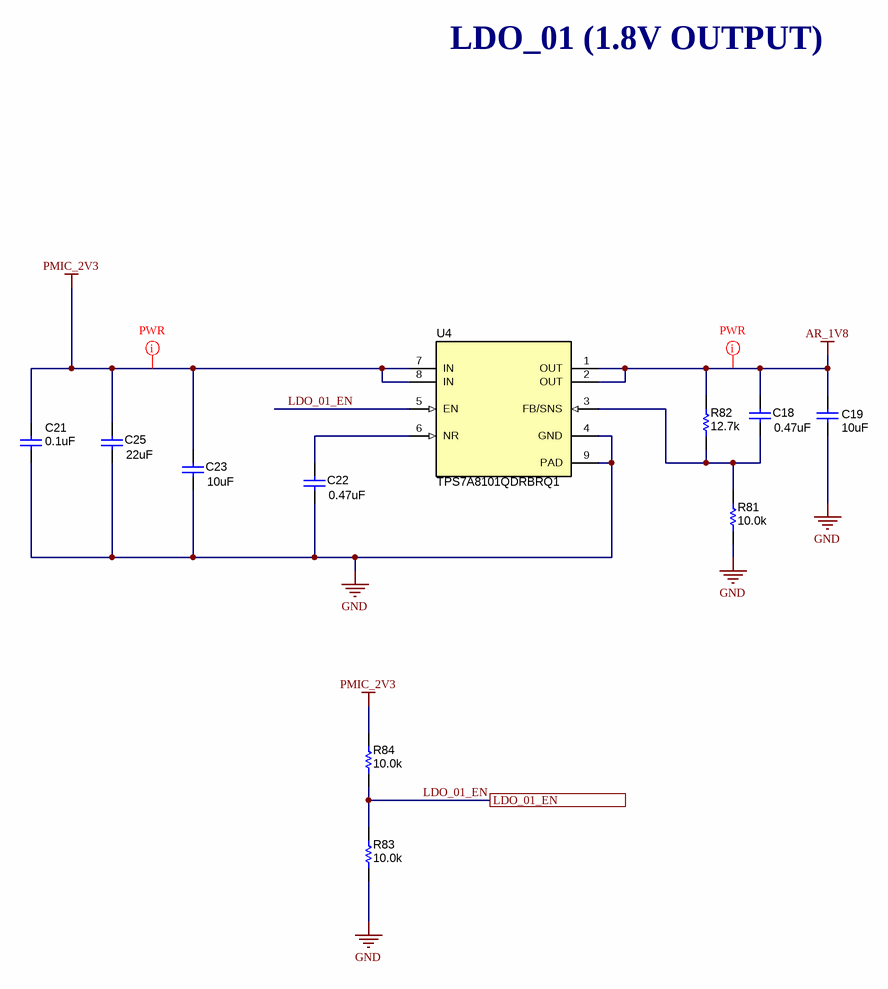
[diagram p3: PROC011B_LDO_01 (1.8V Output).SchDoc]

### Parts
C18  ValueDisplayed: 0.47uF  [0603]  (hidden comment: GCM188R71C474KA55D)
C19  ValueDisplayed: 10uF  [0805_HV]  (hidden comment: GCM21BR71A106KE22L)
C21  ValueDisplayed: 0.1uF  [0402L]  (hidden comment: CGA2B3X7R1H104K050BB)
C22  ValueDisplayed: 0.47uF  [0603]  (hidden comment: GCM188R71C474KA55D)
C23  ValueDisplayed: 10uF  [0805_HV]  (hidden comment: GCM21BR71A106KE22L)
C25  ValueDisplayed: 22uF  [1206_180]  (hidden comment: CGA5L1X7R0J226M160AC)
R81  ValueDisplayed: 10.0k  [0402L]  (hidden comment: CRCW040210K0FKED)
R82  ValueDisplayed: 12.7k  [0402L]  (hidden comment: CRCW040212K7FKED)
R83  ValueDisplayed: 10.0k  [0402L]  (hidden comment: CRCW040210K0FKED)
R84  ValueDisplayed: 10.0k  [0402L]  (hidden comment: CRCW040210K0FKED)
U4  TPS7A8101QDRBRQ1  [DRB0008A]

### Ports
LDO_01_EN

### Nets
AR_1V8: C18.2 C19.2 R82.2 U4.1(OUT) U4.2(OUT)
GND: C19.1 C21.1 C22.1 C23.1 C25.1 R81.1 R83.2 U4.4(GND) U4.9(PAD)
PMIC_2V3: C21.2 C23.2 C25.2 R84.1 U4.7(IN) U4.8(IN)
LDO_01_EN: R83.1 R84.2 U4.5(EN) ; port LDO_01_EN
NetC18_1: C18.1 R81.2 R82.1 U4.3(FB/SNS)
NetC22_2: C22.2 U4.6(NR)

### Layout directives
net class PWR: AR_1V8, PMIC_2V3

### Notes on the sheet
- LDO_01 (1.8V OUTPUT)

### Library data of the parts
C18 C22 = CMP-0007138-4: CAP, CERM, 0.47 uF, 16 V, +/- 10%, X7R, AEC-Q200 Grade 1, 0603; Manufacturer: MuRata; TaMin_C: -55°C; Polarized: N; SizeAreaWB_mm2: 4.68; Value1: Unknown; U/M: EA; Value: 0.47uF; TaMax_C: 125°C; SizeZ_mm: 1; SizeX_mm: 1.6; SizeY_mm: 0.8; Value2: 16V; SizeArea_mm2: 1.28; AEC Qualified: Y; Cap_F: 470nF; AEC Category: Q200
C19 C23 = CMP-0008017-2: as C17 on sheet PROC011B_Decoupling caps
C21 = CMP-0006325-2: CAP, CERM, 0.1 uF, 50 V, +/- 10%, X7R, AEC-Q200 Grade 1, 0402; Manufacturer: TDK; TaMin_C: -55°C; ESR_ohm: 0.039064; Polarized: N; SizeAreaWB_mm2: 3; Value1: 0.039064 ohm; U/M: EA; Value: 0.1uF; TaMax_C: 125°C; SizeZ_mm: 0.6; SizeX_mm: 1; SizeY_mm: 0.5; Cap_Case: 0402; Value2: 50V; AEC Qualified: Y; Cap_F: 100nF; IRMS_A: 8.14669dA; AEC Category: Q200
C25 = CMP-0008770-2: CAP, CERM, 22 uF, 6.3 V, +/- 10%, X7R, AEC-Q200 Grade 1, 1206; Manufacturer: TDK; TaMin_C: -55°C; ESR_ohm: 1.872m; Polarized: N; SizeAreaWB_mm2: 10.92; Value1: 0.001872 ohm; U/M: EA; Value: 22uF; SizeZ_mm: 1.8; SizeX_mm: 3.2; SizeY_mm: 1.6; Value2: 6.3V; SizeArea_mm2: 5.12; AEC Qualified: Y; Cap_F: 22µF; IRMS_A: 5.30203A; AEC Grade: 1; AEC Category: Q200; TaMax_C: 125°C
R81 R84 = CMP-0025958-2: RES, 10.0 k, 1%, 0.063 W, 0402; Manufacturer: Vishay-Dale; Power_W: 63mW; TempCo: 100 ppm/C; Value_Code: 10k0; U/M: EA; Value: 10.0k; EIA_Code: E96; Res_ohm: 10k; SizeX_mm: 1; SizeY_mm: 0.5; SizeZ_mm: 0.6; Value2: 0.063W; VDC_V: 50V; AEC Category: Q200
R82 = CMP-0025993-2: RES, 12.7 k, 1%, 0.063 W, 0402; Manufacturer: Vishay-Dale; Power_W: 63mW; TempCo: 100 ppm/C; Value_Code: 12k7; U/M: EA; Value: 12.7k; EIA_Code: E96; SizeX_mm: 1; SizeY_mm: 0.5; SizeZ_mm: 0.6; Value2: 0.063W; VDC_V: 50V; AEC Category: Q200
R83 = CMP-0025958-2: RES, 10.0 k, 1%, 0.063 W, 0402; Manufacturer: Vishay-Dale; Power_W: 63mW; TempCo: 100 ppm/C; Value_Code: 10k0; U/M: EA; Value: 10.0k; EIA_Code: E96; Res_ohm: 10k; SizeX_mm: 1; SizeY_mm: 0.5; SizeZ_mm: 0.6; Value2: 0.063W; CompType: Resistor; VDC_V: 50V; AEC Category: Q200; INSTALATION: DNP
U4 = CMP-0073870-2: Automotive Low-Noise, Wide-Bandwidth, High PSRR, Low-Dropout 1-A Linear Regulator, DRB0008A (VSON-8); Manufacturer: Texas Instruments; SizeZ_mm: 1.0; SizeX_mm: 3.0; SizeArea_mm2: 9.0; CompType: IC; U/M: EA; SizeAreaWB_mm2: 16.0

## Sheet PROC011B_LDO_02 (1.3V Output).SchDoc: LDO_02 (1.3V Output)
size 431 x 279 mm; Date: Not shown in title block; ApprovedBy: Not shown in title block; CheckedBy: Not shown in title block; Author: Not shown in title block; CompanyName: Not shown in title block; Engineer: Not shown in title block; Organization: Not shown in title block; Address1: Not shown in title block; Address2: Not shown in title block; Address3: Not shown in title block; Address4: Not shown in title block; DocumentNumber: 1; Revision: Use project parameter SCH_Rev; SheetNumber: 5; SheetTotal: 17; PageSetup: Record=PageOptions¦CenterHorizontal=True¦CenterVertical=True¦PrintScale=1.00¦XCorrection=1.00¦YCorrection=1.00¦PrintKind=0¦BorderSize=5000000¦LeftOffset=0¦BottomOffset=0¦Orientation=2¦PaperLength=1000¦PaperWidth=1000¦Scale=100¦PaperSource=15¦PrintQuality=600¦MediaType=1¦DitherType=10¦PaperKind=Letter¦PrintScaleMode=1
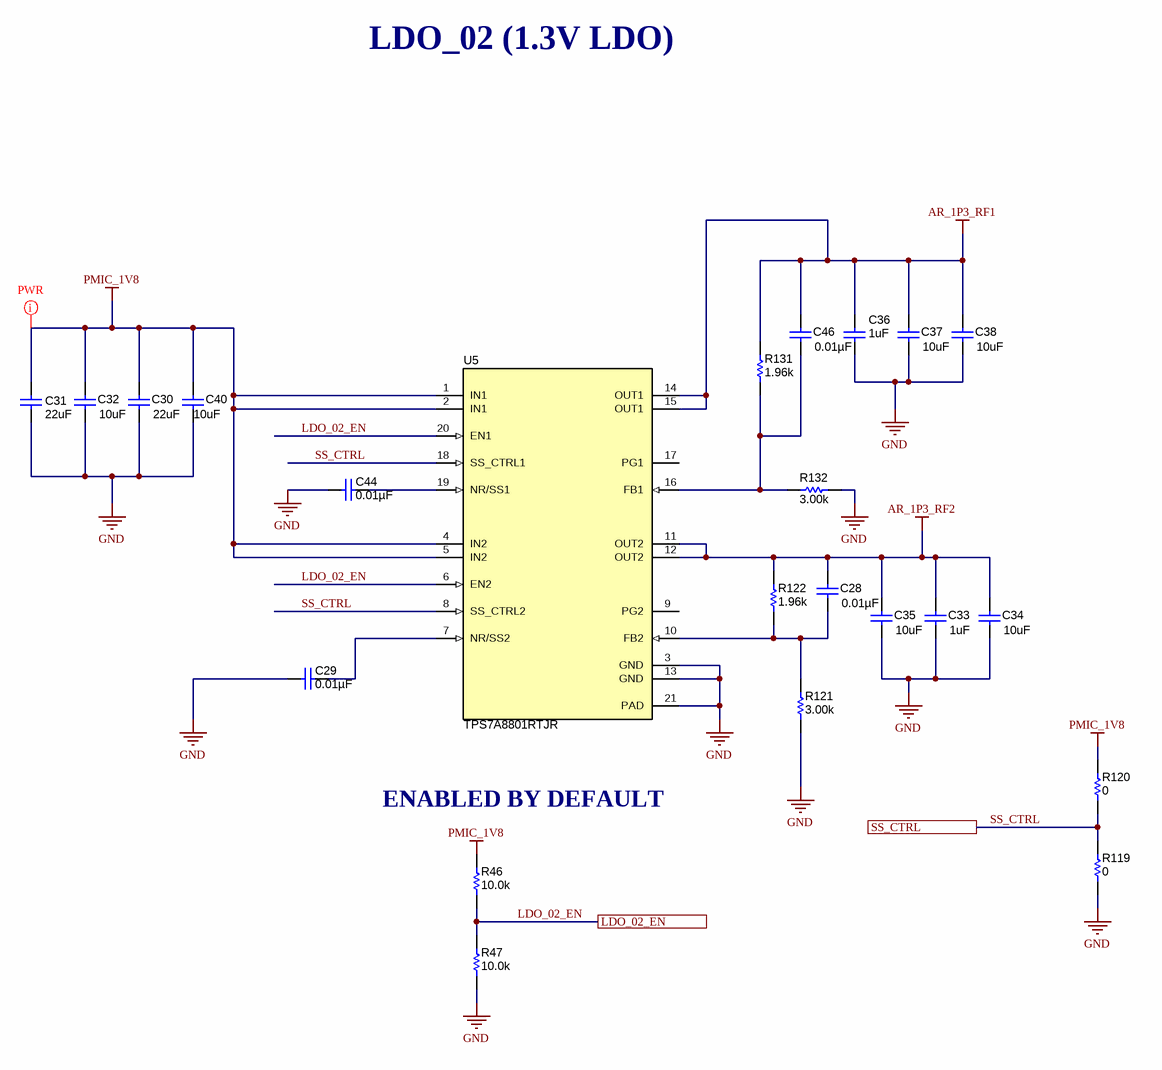
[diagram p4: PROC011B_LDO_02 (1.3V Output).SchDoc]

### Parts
C28  ValueDisplayed: 0.01µF  [0402L]  (hidden comment: CGA2B3X8R1H103K050BB)
C29  ValueDisplayed: 0.01µF  [0402L]  (hidden comment: CGA2B3X8R1H103K050BB)
C30  ValueDisplayed: 22uF  [1206_180]  (hidden comment: CGA5L1X7R0J226M160AC)
C31  ValueDisplayed: 22uF  [1206_180]  (hidden comment: CGA5L1X7R0J226M160AC)
C32  ValueDisplayed: 10uF  [0805_HV]  (hidden comment: GCM21BR71A106KE22L)
C33  ValueDisplayed: 1uF  [0603]  (hidden comment: GCM188R71C105KA64D)
C34  ValueDisplayed: 10uF  [0805_HV]  (hidden comment: GCM21BR71A106KE22L)
C35  ValueDisplayed: 10uF  [0805_HV]  (hidden comment: GCM21BR71A106KE22L)
C36  ValueDisplayed: 1uF  [0603]  (hidden comment: GCM188R71C105KA64D)
C37  ValueDisplayed: 10uF  [0805_HV]  (hidden comment: GCM21BR71A106KE22L)
C38  ValueDisplayed: 10uF  [0805_HV]  (hidden comment: GCM21BR71A106KE22L)
C40  ValueDisplayed: 10uF  [0805_HV]  (hidden comment: GCM21BR71A106KE22L)
C44  ValueDisplayed: 0.01µF  [0402L]  (hidden comment: CGA2B3X8R1H103K050BB)
C46  ValueDisplayed: 0.01µF  [0402L]  (hidden comment: CGA2B3X8R1H103K050BB)
R46  ValueDisplayed: 10.0k  [0402L]  (hidden comment: CRCW040210K0FKED)
R47  ValueDisplayed: 10.0k  [0402L]  (hidden comment: CRCW040210K0FKED)
R119  ValueDisplayed: 0  [0402L]  (hidden comment: ERJ-2GE0R00X)
R120  ValueDisplayed: 0  [0402L]  (hidden comment: ERJ-2GE0R00X)
R121  ValueDisplayed: 3.00k  [0402L]  (hidden comment: CRCW04023K00FKED)
R122  ValueDisplayed: 1.96k  [0402L]  (hidden comment: CRCW04021K96FKED)
R131  ValueDisplayed: 1.96k  [0402L]  (hidden comment: CRCW04021K96FKED)
R132  ValueDisplayed: 3.00k  [0402L]  (hidden comment: CRCW04023K00FKED)
U5  TPS7A8801RTJR  [RTJ0020D]

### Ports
LDO_02_EN, SS_CTRL

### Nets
AR_1P3_RF1: C36.2 C37.2 C38.2 C46.2 R131.2 U5.14(OUT1) U5.15(OUT1)
AR_1P3_RF2: C28.2 C33.2 C34.2 C35.2 R122.2 U5.11(OUT2) U5.12(OUT2)
GND: C29.1 C30.1 C31.1 C32.1 C33.1 C34.1 C35.1 C36.1 C37.1 C38.1 C40.1 C44.1 R47.2 R119.1 R121.1 R132.1 U5.3(GND) U5.13(GND) U5.21(PAD)
PMIC_1V8: C30.2 C31.2 C32.2 C40.2 R46.1 R120.2 U5.1(IN1) U5.2(IN1) U5.4(IN2) U5.5(IN2)
LDO_02_EN: R46.2 R47.1 U5.6(EN2) U5.20(EN1) ; port LDO_02_EN
SS_CTRL: R119.2 R120.1 U5.8(SS_CTRL2) U5.18(SS_CTRL1) ; port SS_CTRL
NetC28_1: C28.1 R121.2 R122.1 U5.10(FB2)
NetC29_2: C29.2 U5.7(NR/SS2)
NetC44_2: C44.2 U5.19(NR/SS1)
NetC46_1: C46.1 R131.1 R132.2 U5.16(FB1)

Not connected (* = marked no-connect by the designer): U5 9(PG2) 17(PG1)

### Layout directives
net class PWR: PMIC_1V8

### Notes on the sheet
- LDO_02 (1.3V LDO)
- ENABLED BY DEFAULT

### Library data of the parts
C28 C29 C44 C46 = CMP-0078224-1: CAP, CERM, 0.01 µF, 50 V,+/- 10%, X8R, AEC-Q200 Grade 0, 0402; Manufacturer: TDK; TaMin_C: -55°C; Polarized: N; SizeAreaWB_mm2: 3; U/M: EA; Value: 0.01uF; TaMax_C: 150°C; SizeZ_mm: 0.6; SizeX_mm: 1; SizeY_mm: 0.5; Cap_Case: 0402; Value2: 50V; AEC Qualified: Y; Cap_F: 10nF; AEC Grade: 0; AEC Category: Q200
C30 C31 = CMP-0008770-2: as C25 on sheet PROC011B_LDO_01 (1.8V Output)
C32 C34 C35 C37 C38 C40 = CMP-0008017-2: as C17 on sheet PROC011B_Decoupling caps
C33 C36 = CMP-0007136-5: as C13 on sheet PROC011B_Decoupling caps
R46 = CMP-0025958-2: as R81 on sheet PROC011B_LDO_01 (1.8V Output)
R47 = CMP-0025958-2: as R83 on sheet PROC011B_LDO_01 (1.8V Output)
R119 = CMP-0026992-2: RES, 0, 5%, 0.063 W, 0402; Manufacturer: Panasonic; Power_W: 63mW; TempCo: 600 ppm/C; Value_Code: 0000; U/M: EA; Value: 0; EIA_Code: E24; SizeX_mm: 1; SizeY_mm: 0.5; SizeZ_mm: 0.6; Value2: 0.063W; VDC_V: 50V; AEC Category: Q200
R120 = CMP-0026992-2: RES, 0, 5%, 0.063 W, 0402; Manufacturer: Panasonic; Power_W: 63mW; TempCo: 600 ppm/C; Value_Code: 0000; U/M: EA; Value: 0; EIA_Code: E24; SizeX_mm: 1; SizeY_mm: 0.5; SizeZ_mm: 0.6; Value2: 0.063W; CompType: Resistor; VDC_V: 50V; AEC Category: Q200; INSTALATION: DNP
R121 = CMP-0078211-1: RES, 3.00 k, 1%, 0.063 W, AEC-Q200 Grade 0, 0402; Manufacturer: Vishay-Dale; Value_Code: 3k00; SizeArea_mm2: 0.5; AEC Qualified: Y; AEC Category: Q200; Res_ohm: 3k; Value: 3.00k; SizeZ_mm: 0.6; TempCo: 100 ppm/C; AEC Grade: 0; Power_W: 63mW; VDC_V: 50V; Value2: 0.063W; U/M: EA; CompType: Resistor; SizeX_mm: 1
R122 R131 = CMP-0026099-1: RES, 1.96 k, 1%, 0.063 W, 0402; Manufacturer: Vishay-Dale; Power_W: 63mW; TempCo: 100 ppm/C; Value_Code: 1k96; U/M: EA; Value: 1.96k; EIA_Code: E96; SizeX_mm: 1; SizeY_mm: 0.5; SizeZ_mm: 0.6; Value2: 0.063W; CompType: Resistor; VDC_V: 50V; AEC Category: Q200
R132 = CMP-0078211-1: RES, 3.00 k, 1%, 0.063 W, AEC-Q200 Grade 0, 0402; Manufacturer: Vishay-Dale; Value_Code: 3k00; SizeArea_mm2: 0.5; AEC Qualified: Y; AEC Category: Q200; Res_ohm: 3k; Value: 3.00k; SizeZ_mm: 0.6; TempCo: 100 ppm/C; AEC Grade: 0; Power_W: 63mW; VDC_V: 50V; Value2: 0.063W; U/M: EA; SizeX_mm: 1
U5 = CMP-0073732-2: Dual, 1-A, Low Noise (3.8-uVRMS), LDO Voltage Regulator, RTJ0020D (WQFN-20); Alternate PartNumber: TPS7A8801RTJT; Alternate Manufacturer: Texas Instruments; Green_Lifecycle: Active; SizeAreaWB_mm2: 25.0; Green_REACh: Passed; U/M: EA; SizeZ_mm: 0.8; SizeX_mm: 4.0; SizeArea_mm2: 16.0; CompType: IC

## Sheet PROC011B_VPP_Supply.SchDoc: VPP_Supply
size 431 x 279 mm; Date: Not shown in title block; ApprovedBy: Not shown in title block; CheckedBy: Not shown in title block; Author: Not shown in title block; CompanyName: Not shown in title block; Engineer: Not shown in title block; Organization: Not shown in title block; Address1: Not shown in title block; Address2: Not shown in title block; Address3: Not shown in title block; Address4: Not shown in title block; DocumentNumber: 1; Revision: Use project parameter SCH_Rev; SheetNumber: 6; SheetTotal: 17; PageSetup: Record=PageOptions¦CenterHorizontal=True¦CenterVertical=True¦PrintScale=1.00¦XCorrection=1.00¦YCorrection=1.00¦PrintKind=0¦BorderSize=5000000¦LeftOffset=0¦BottomOffset=0¦Orientation=2¦PaperLength=1000¦PaperWidth=1000¦Scale=100¦PaperSource=15¦PrintQuality=600¦MediaType=1¦DitherType=10¦PaperKind=Letter¦PrintScaleMode=1
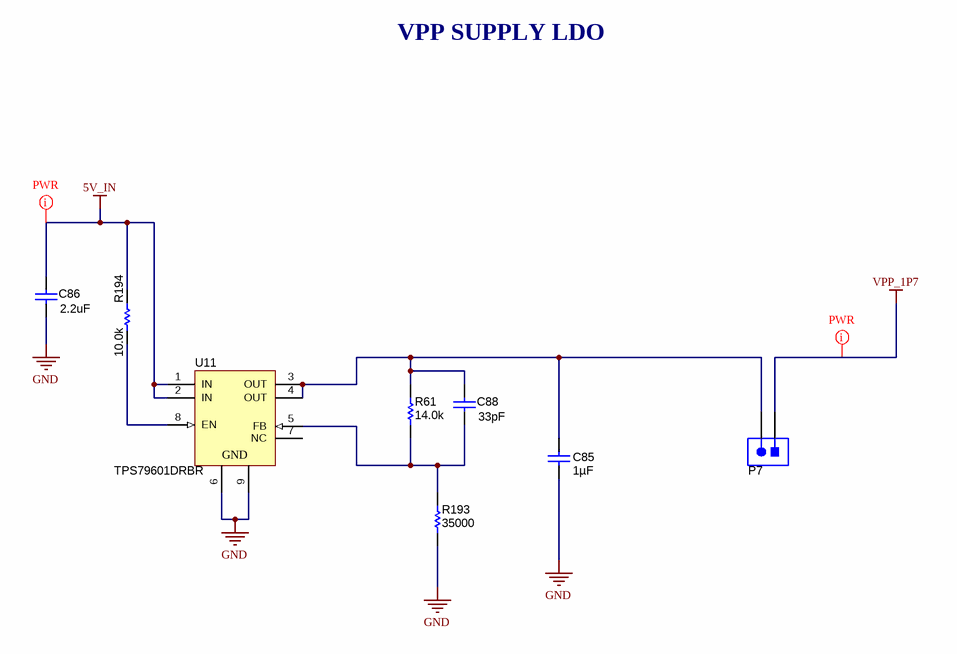
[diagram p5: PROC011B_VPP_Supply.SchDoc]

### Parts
C85  ValueDisplayed: 1µF  [0402L]  (hidden comment: C1005X7S0J105M050BC)
C86  ValueDisplayed: 2.2uF  [0402_065L]  (hidden comment: C1005X7S1A225K050BC)
C88  ValueDisplayed: 33pF  [0402L]  (hidden comment: C0402C330J5GAC)
P7  TSW-102-07-G-S  [TSW-102-07-X-S]  (value not drawn)
R61  ValueDisplayed: 14.0k  [0402L]  (hidden comment: CRCW040214K0FKED)
R193  ValueDisplayed: 35000  [0402L]  (hidden comment: PNM0402E3502BST1)
R194  ValueDisplayed: 10.0k  [0402L]  (hidden comment: CRCW040210K0FKED)
U11  TPS79601DRBR  [DRB0008B]

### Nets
5V_IN: C86.2 R194.1 U11.1(IN) U11.2(IN)
GND: C85.1 C86.1 R193.1 U11.6(GND) U11.9(GND)
VPP_1P7: P7.1
NetC85_2: C85.2 C88.1 P7.2 R61.2 U11.3(OUT) U11.4(OUT)
NetC88_2: C88.2 R61.1 R193.2 U11.5(FB)
NetR194_2: R194.2 U11.8(EN)

Not connected (* = marked no-connect by the designer): U11 7(NC)

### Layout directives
net class PWR: 5V_IN, VPP_1P7

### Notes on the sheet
- VPP SUPPLY LDO

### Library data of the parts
C85 = CMP-0078222-1: CAP, CERM, 1 µF, 6.3 V,+/- 20%, X7S, 0402; Manufacturer: TDK; TaMin_C: -55°C; Polarized: N; SizeAreaWB_mm2: 3; U/M: EA; Value: 1uF; TaMax_C: 125°C; SizeZ_mm: 0.6; SizeX_mm: 1; SizeY_mm: 0.5; Cap_Case: 0402; Value2: 6.3V; AEC Category: Q200
C86 = CMP-0006302-2: CAP, CERM, 2.2 uF, 10 V, +/- 10%, X7S, 0402; Manufacturer: TDK; TaMin_C: -55°C; ESR_ohm: 5.925m; Polarized: N; SizeAreaWB_mm2: 3; Value1: 0.005925 ohm; U/M: EA; Value: 2.2uF; TaMax_C: 125°C; SizeZ_mm: 0.65; SizeX_mm: 1; SizeY_mm: 0.5; Cap_Case: 0402_065; Value2: 10V; CompType: Capacitor; Cap_F: 2.2µF; IRMS_A: 2.05591A; AEC Category: Q200
C88 = CMP-0006242-2: CAP, CERM, 33 pF, 50 V, +/- 5%, C0G/NP0, 0402; Manufacturer: Kemet; TaMin_C: -55°C; Polarized: N; SizeAreaWB_mm2: 3; Value1: Unknown; U/M: EA; Value: 33pF; TaMax_C: 125°C; SizeZ_mm: 0.6; SizeX_mm: 1; SizeY_mm: 0.5; Cap_Case: 0402; Value2: 50V; AEC Category: Q200
P7 = CMP-0075405-1: Header, 100mil, 2x1, Gold, TH; Manufacturer: Samtec; Pitch_mm: 2.54; Cert_VDE: N; Gender: Male; Cert_CSA: Y; Voltage_V: 550V; Green_REACh: Passed; Current_A: 6.3A; CT: False; Green_Lifecycle: Active; Row_Count: 1; CNHeader: True
R61 = CMP-0026015-2: RES, 14.0 k, 1%, 0.063 W, 0402; Manufacturer: Vishay-Dale; Power_W: 63mW; TempCo: 100 ppm/C; Value_Code: 14k0; U/M: EA; Value: 14.0k; EIA_Code: E96; Res_ohm: 14k; SizeX_mm: 1; SizeY_mm: 0.5; SizeZ_mm: 0.6; Value2: 0.063W; VDC_V: 50V; AEC Category: Q200
R193 = CMP-0078213-1: RES, 35000, 0.1%, 0.05 W, 0402; Manufacturer: Vishay-Dale; Value_Code: 35k0; SizeArea_mm2: 0.5; AEC Qualified: N; AEC Category: Q200; Res_ohm: 35k; Value: 35.0k; SizeZ_mm: 0.6; TempCo: 25 ppm/C; Power_W: 50mW; VDC_V: 75V; Value2: 0.05W; U/M: EA; SizeX_mm: 1
R194 = CMP-0025958-2: as R81 on sheet PROC011B_LDO_01 (1.8V Output)
U11 = CMP-0036402-2: Single Output High PSRR LDO, 1 A, Adjustable 1.2 to 5.5 V Output, 2.7 to 5.5 V Input, 8-pin SON (DRB), -40 to 125 degC, Green (RoHS & no Sb/Br); Manufacturer: Texas Instruments; Vin(Min)(V): 2.7; Vout Adj(Max)(V): 5.5; Vout Adj(Min)(V): 1.2; Accuracy(%): 2; SubFamily: Single Channel LDO; Iq(Typ)(mA): 0.26; Vdo(Typ)(mV): 250; Iout(Max)(A): 1

## Sheet PROC011B_Pwr_RST_LEDs.SchDoc: Pwr_RST_LEDs
size 431 x 279 mm; Date: Not shown in title block; ApprovedBy: Not shown in title block; CheckedBy: Not shown in title block; Author: Not shown in title block; CompanyName: Not shown in title block; Engineer: Not shown in title block; Organization: Not shown in title block; Address1: Not shown in title block; Address2: Not shown in title block; Address3: Not shown in title block; Address4: Not shown in title block; DocumentNumber: 1; Revision: Use project parameter SCH_Rev; SheetNumber: 7; SheetTotal: 17; PageSetup: Record=PageOptions¦CenterHorizontal=True¦CenterVertical=True¦PrintScale=1.00¦XCorrection=1.00¦YCorrection=1.00¦PrintKind=0¦BorderSize=5000000¦LeftOffset=0¦BottomOffset=0¦Orientation=2¦PaperLength=1000¦PaperWidth=1000¦Scale=100¦PaperSource=15¦PrintQuality=600¦MediaType=1¦DitherType=10¦PaperKind=Letter¦PrintScaleMode=1
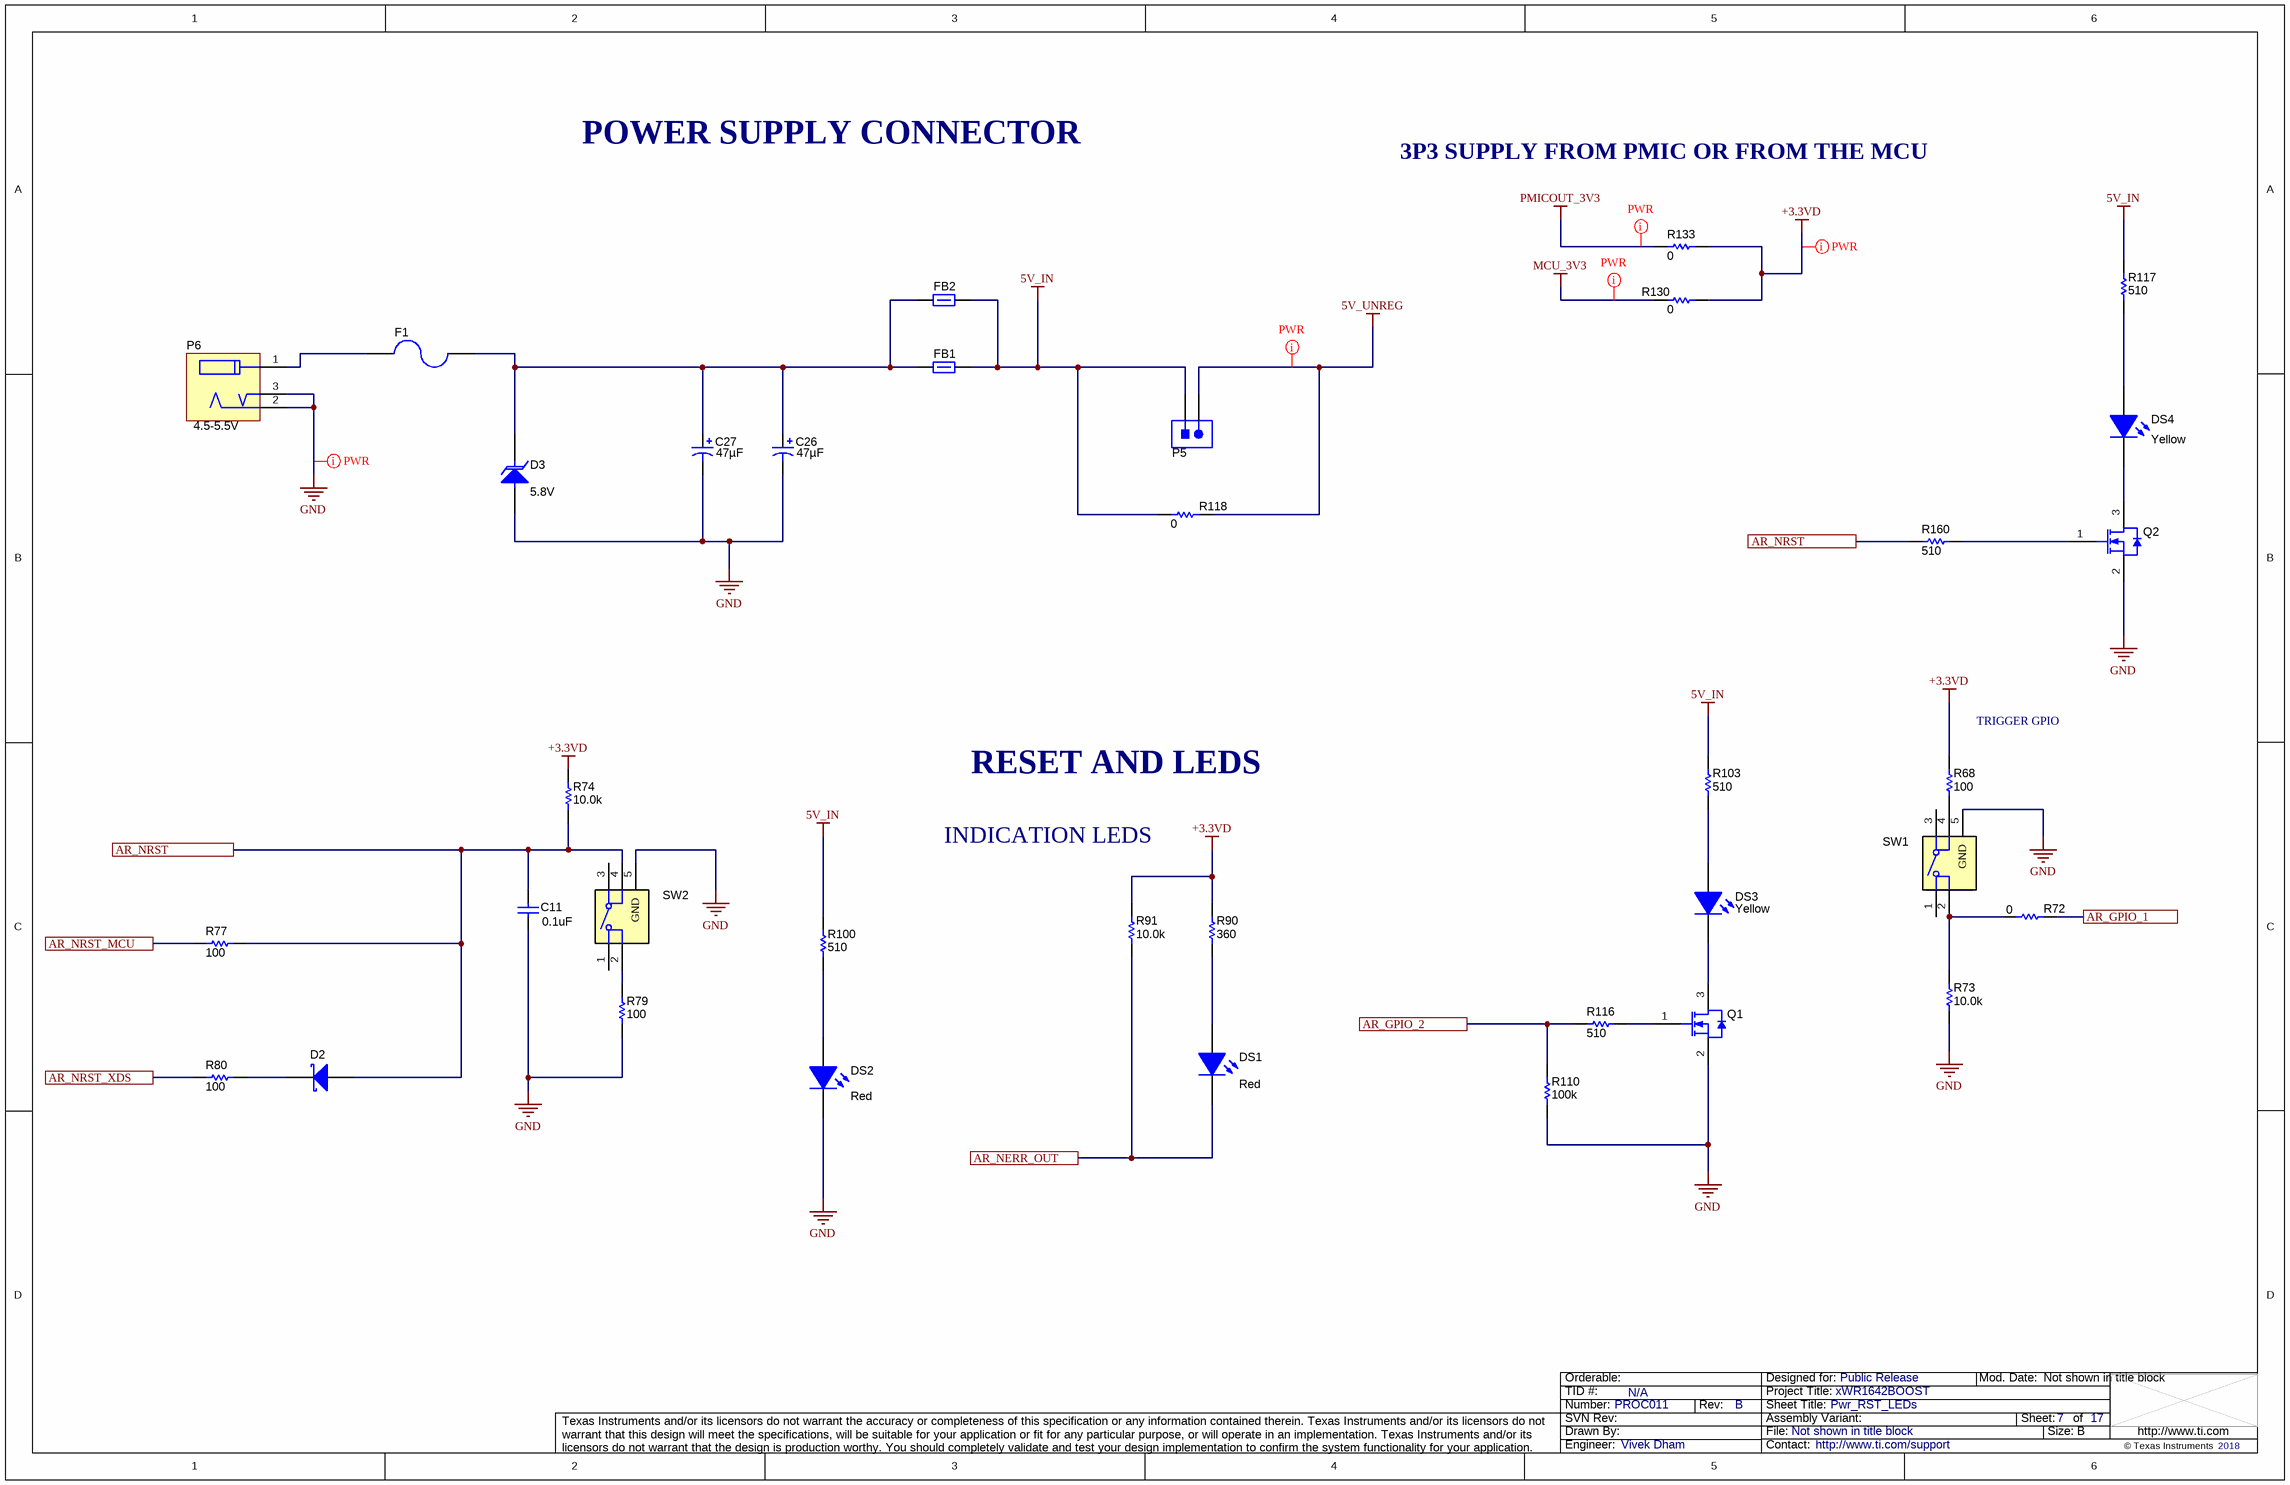
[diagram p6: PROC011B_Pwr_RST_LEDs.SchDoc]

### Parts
C11  ValueDisplayed: 0.1uF  [0402L]  (hidden comment: GCM155R71C104KA55D)
C26  ValueDisplayed: 47µF  [3528-21]  (hidden comment: T491B476K010AT)
C27  ValueDisplayed: 47µF  [3528-21]  (hidden comment: T491B476K010AT)
D2  SMS3923-040LF  [SOD-882]  (value not drawn)
D3  value 5.8V  [SMB]  (hidden comment: SZP6SMB6.8AT3G)
DS1  value Red  [TLMx1000_Red]  (hidden comment: TLMS1000-GS08)
DS2  value Red  [TLMx1000_Red]  (hidden comment: TLMS1000-GS08)
DS3  value Yellow  [TLMx1000_Yellow]  (hidden comment: TLMY1000-GS08)
DS4  value Yellow  [TLMx1000_Yellow]  (hidden comment: TLMY1000-GS08)
F1  0440005.WR  [1206]  (value not drawn)
FB1  BLM21PG300SH1D  [0805_HV]  (value not drawn)
FB2  BLM21PG300SH1D  [0805_HV]  (value not drawn)
P5  TSW-102-07-G-S  [TSW-102-07-X-S]  (value not drawn)
P6  Voltage_V: 4.5-5.5V  [CUI_PJ-002AH]  (hidden comment: PJ-002AH)
Q1  BSS123  [SOT-23]  (value not drawn)
Q2  BSS123  [SOT-23]  (value not drawn)
R68  ValueDisplayed: 100  [0402L]  (hidden comment: ERJ-2GEJ101X)
R72  ValueDisplayed: 0  [0201_Silk]  (hidden comment: CRCW02010000Z0ED)
R73  ValueDisplayed: 10.0k  [0402L]  (hidden comment: CRCW040210K0FKED)
R74  ValueDisplayed: 10.0k  [0402L]  (hidden comment: CRCW040210K0FKED)
R77  ValueDisplayed: 100  [0402L]  (hidden comment: ERJ-2GEJ101X)
R79  ValueDisplayed: 100  [0402L]  (hidden comment: ERJ-2GEJ101X)
R80  ValueDisplayed: 100  [0402L]  (hidden comment: ERJ-2GEJ101X)
R90  ValueDisplayed: 360  [0402L]  (hidden comment: ERJ-2GEJ361X)
R91  ValueDisplayed: 10.0k  [0402L]  (hidden comment: CRCW040210K0FKED)
R100  ValueDisplayed: 510  [0402L]  (hidden comment: ERJ-2GEJ511X)
R103  ValueDisplayed: 510  [0402L]  (hidden comment: ERJ-2GEJ511X)
R110  ValueDisplayed: 100k  [0402L]  (hidden comment: CRCW0402100KFKED)
R116  ValueDisplayed: 510  [0402L]  (hidden comment: ERJ-2GEJ511X)
R117  ValueDisplayed: 510  [0402L]  (hidden comment: ERJ-2GEJ511X)
R118  ValueDisplayed: 0  [2010]  (hidden comment: CRCW20100000Z0EF)
R130  ValueDisplayed: 0  [0603]  (hidden comment: MCT06030Z0000ZP500)
R133  ValueDisplayed: 0  [0603]  (hidden comment: MCT06030Z0000ZP500)
R160  ValueDisplayed: 510  [0402L]  (hidden comment: ERJ-2GEJ511X)
SW1  KMR243GLFG  [SW_KMR243GLFG]  (value not drawn)
SW2  KMR243GLFG  [SW_KMR243GLFG]  (value not drawn)

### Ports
AR_GPIO_1, AR_GPIO_2, AR_NERR_OUT, AR_NRST, AR_NRST_MCU, AR_NRST_XDS

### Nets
5V_IN: FB1.2 FB2.2 P5.1 R100.2 R103.2 R117.2 R118.1
5V_UNREG: P5.2 R118.2
+3.3VD: R68.2 R74.2 R90.2 R91.2 R130.2 R133.2
GND: C11.1 C26.2(-) C27.2(-) D3.2(A) DS2.2(K) P6.2 P6.3 Q1.2(S) Q2.2(S) R73.1 R79.1 R110.1 SW1.5(GND) SW2.5(GND)
MCU_3V3: R130.1
PMICOUT_3V3: R133.1
AR_GPIO_1: R72.2 ; port AR_GPIO_1
AR_GPIO_2: R110.2 R116.1 ; port AR_GPIO_2
AR_NERR_OUT: DS1.2(K) R91.1 ; port AR_NERR_OUT
AR_NRST: C11.2 D2.2(A) R74.1 R77.2 R160.1 SW2.4 ; port AR_NRST
AR_NRST_MCU: R77.1 ; port AR_NRST_MCU
AR_NRST_XDS: R80.1 ; port AR_NRST_XDS
NetC26_1: C26.1(+) C27.1(+) D3.1(K) F1.1 FB1.1 FB2.1
NetD2_1: D2.1(K) R80.2
NetDS1_1: DS1.1(A) R90.1
NetDS2_1: DS2.1(A) R100.1
NetDS3_1: DS3.1(A) R103.1
NetDS3_2: DS3.2(K) Q1.3(D)
NetDS4_1: DS4.1(A) R117.1
NetDS4_2: DS4.2(K) Q2.3(D)
NetF1_2: F1.2 P6.1
NetQ1_1: Q1.1(G) R116.2
NetQ2_1: Q2.1(G) R160.2
NetR68_1: R68.1 SW1.4
NetR72_1: R72.1 R73.2 SW1.2
NetR79_2: R79.2 SW2.2

Not connected (* = marked no-connect by the designer): SW1 1 3; SW2 1 3

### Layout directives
net class PWR: 5V_UNREG, +3.3VD, GND, MCU_3V3, PMICOUT_3V3

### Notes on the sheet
- POWER SUPPLY CONNECTOR
- 3P3 SUPPLY FROM PMIC OR FROM THE MCU
- (near R68) TRIGGER GPIO
- RESET AND LEDS
- INDICATION LEDS

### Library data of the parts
C11 = CMP-0006351-2: as C4 on sheet PROC011B_Decoupling caps
C26 C27 = CMP-0078216-1: CAP, TA, 47 µF, 10 V, +/- 10%, SMD; Manufacturer: Kemet; TaMin_C: -55°C; Polarized: Y; SizeAreaWB_mm2: 17.1; Value: 47uF; TaMax_C: 125°C; SizeZ_mm: 2.1; SizeX_mm: 3.5; SizeY_mm: 2.8; Value2: 10V; SizeArea_mm2: 9.8; CompType: Capacitor; AEC Qualified: N; AEC Category: Q200
D2 = CMP-0078187-1: Diode, Schottky,  V, 0.01 A, SOD-882; Manufacturer: Skyworks Solutions; SizeAreaWB_mm2: 3.2; SizeArea_mm2: 0.6; AEC Qualified: N; TJmax_C: 150°C; AEC Category: Q101; SizeZ_mm: 0.5; Io_A: 10mA; Vf_V: 3.4dV; Value2: 0.34V; Value1: 0.01A; SizeX_mm: 1
D3 = CMP-0078243-1: Diode, TVS, Uni, 5.8 V, 10.5 Vc, AEC-Q101, SMB; Manufacturer: Littelfuse; Power_W: 550mW; SizeAreaWB_mm2: 44.156; Value1: 0.55W; RJA_CperW: 226; SizeZ_mm: 2.6; SizeX_mm: 5.6; SizeY_mm: 3.81; SizeArea_mm2: 21.336; AEC Qualified: Y; AEC Category: Q101
DS1 DS2 = CMP-0078197-1: LED, Red, SMD; Manufacturer: Vishay-Semiconductor; Tjmax_C: 120°C; SizeAreaWB_mm2: 4.68; Vr_V: 6V; Power_TotalModule: 40mW; Angle: 160; SizeArea_mm2: 1.28; Ir_A: 10µA; SizeZ_mm: 0.65; Io_A: 2mA; Vf_V: 1.8V; SizeY_mm: 0.8; U/M: EA; Value1: .04W; SizeX_mm: 1.6; Type: AlInGaP
DS3 DS4 = CMP-0078196-1: LED, Yellow, SMD; Manufacturer: Vishay-Semiconductor; Tjmax_C: 120°C; SizeAreaWB_mm2: 4.68; Vr_V: 6V; Power_TotalModule: 40mW; Angle: 160; SizeArea_mm2: 1.28; Ir_A: 10µA; SizeZ_mm: 0.65; Io_A: 2mA; Vf_V: 1.8V; SizeY_mm: 0.8; U/M: EA; Value1: .04W; SizeX_mm: 1.6; Type: AlInGaP
F1 = CMP-0003458-1: Fuse, 5 A, 32VAC/VDC, SMD; Manufacturer: Littelfuse; Irating_A: 5A; SizeAreaWB_mm2: 10.92; Interrupt_AC: 50A; VAC_V: 32V; SizeZ_mm: 1.35; SizeX_mm: 3.2; SizeY_mm: 1.6; SizeArea_mm2: 5.12; Rtyp_Ohm: 0.012; MeltingTyp: 4.761
FB1 = CMP-0003364-1: Ferrite Bead, 30 ohm @ 100 MHz, 4 A, 0805; Manufacturer: MuRata; ZTyp@100MHz_Ohm: 30; SizeAreaWB_mm2: 6.75; DCR_ohm: 0.014; Value1: 0.014 ohm; Value: 30 ohm; Imax_A: 4A; SizeZ_mm: 1.45; SizeX_mm: 2; SizeY_mm: 1.25; SizeArea_mm2: 2.5
FB2 = CMP-0003364-1: Ferrite Bead, 30 ohm @ 100 MHz, 4 A, 0805; Manufacturer: MuRata; ZTyp@100MHz_Ohm: 30; SizeAreaWB_mm2: 6.75; DCR_ohm: 0.014; Value1: 0.014 ohm; Value: 30 ohm; Imax_A: 4A; SizeZ_mm: 1.45; SizeX_mm: 2; SizeY_mm: 1.25; SizeArea_mm2: 2.5; INSTALLATION: DNP
P5 = CMP-0075405-1: as P7 on sheet PROC011B_VPP_Supply
P6 = CMP-0078270-1: DC POWER JACK, R/A, TH; Manufacturer: CUI Inc.; Gender: Female; Cert_UL: Y; Current_A: 5A; Green_REACh: Incomplete; Green_Lifecycle: Not Set
Q1 Q2 = CMP-0000947-2: MOSFET, N-CH, 100 V, 0.17 A, SOT-23; Alternate Manufacturer: None; Manufacturer: Fairchild Semiconductor; SizeZ_mm: 1.1; ChType: N; Value2: 1.8 nC; Value1: 1; VdsMax_V: 100V; SizeX_mm: 2.5; SizeY_mm: 3; Vgs_V: 20V; Value: 100V; Rdson45_ohm: 10; SizeArea_mm2: 7.5; AEC Category: Q101; IdsMax_A: 1.7dA; SizeAreaWB_mm2: 14; U/M: EA; QgTyp_nC: 1.8
R68 R77 R79 R80 = CMP-0026993-2: RES, 100, 5%, 0.1 W, AEC-Q200 Grade 0, 0402; Manufacturer: Panasonic; Power_W: 100mW; TempCo: 200 ppm/C; Value_Code: 100R; U/M: EA; Value: 100; EIA_Code: E24; SizeX_mm: 1; SizeY_mm: 0.5; SizeZ_mm: 0.6; Value2: 0.1W; AEC Qualified: Y; AEC Grade: 0; AEC Category: Q200
R72 = CMP-0027008-3: RES, 0, 5%, 0.05 W, 0201; Manufacturer: Vishay-Dale; Power_W: 50mW; TempCo: ppm/C; Value_Code: 0000; U/M: EA; Value: 0; EIA_Code: E24; SizeX_mm: 0.6; SizeY_mm: 0.3; SizeZ_mm: 0.26; Value2: 0.05W; SizeArea_mm2: 0.18; AEC Qualified: N; AEC Category: Q200
R73 R74 R91 = CMP-0025958-2: as R81 on sheet PROC011B_LDO_01 (1.8V Output)
R90 = CMP-0078194-1: RES, 360, 5%, 0.1 W, AEC-Q200 Grade 0, 0402; Manufacturer: Panasonic; Value_Code: 360R; SizeArea_mm2: 0.5; AEC Qualified: Y; AEC Category: Q200; Value: 360; SizeZ_mm: 0.6; EIA_Code: E24; TempCo: 200 ppm/C; AEC Grade: 0; Power_W: 100mW; VDC_V: 50V; Value2: 0.1W; U/M: EA; SizeX_mm: 1
R100 R103 R116 R117 R160 = CMP-0078212-1: RES, 510, 5%, 0.1 W, AEC-Q200 Grade 0, 0402; Manufacturer: Panasonic; Value_Code: 510R; SizeArea_mm2: 0.5; AEC Qualified: Y; AEC Category: Q200; Value: 510; SizeZ_mm: 0.6; EIA_Code: E24; TempCo: 200 ppm/C; AEC Grade: 0; Power_W: 100mW; VDC_V: 50V; Value2: 0.1W; U/M: EA; SizeX_mm: 1
R110 = CMP-0025950-2: RES, 100 k, 1%, 0.063 W, 0402; Manufacturer: Vishay-Dale; Power_W: 63mW; TempCo: 100 ppm/C; U/M: EA; Value: 100k; EIA_Code: E96; SizeX_mm: 1; SizeY_mm: 0.5; SizeZ_mm: 0.6; Value2: 0.063W; VDC_V: 50V; AEC Category: Q200
R118 = CMP-0016044-2: RES, 0, 5%, 0.75 W, AEC-Q200 Grade 0, 2010; Manufacturer: Vishay-Dale; Power_W: 750mW; TempCo: ppm/C; Value_Code: 0000; U/M: EA; Value: 0; EIA_Code: E24; SizeX_mm: 5; SizeY_mm: 2.5; SizeZ_mm: 1.66; Value2: 0.75W; SizeArea_mm2: 12.5; AEC Qualified: Y; AEC Category: Q200
R130 = CMP-0025884-3: as R137 on sheet PROC011B_Decoupling caps
R133 = CMP-0025884-3: RES, 0, 5%, 0.125 W, 0603; Manufacturer: Vishay/Beyschlag; Power_W: 125mW; TempCo: ppm/C; Value_Code: 0000; U/M: EA; Value: 0; EIA_Code: E24; SizeX_mm: 1.6; SizeY_mm: 0.8; SizeZ_mm: 1; Value2: 0.125W; SizeArea_mm2: 1.28; AEC Qualified: N; AEC Category: Q200
SW1 SW2 = CMP-0002325-1: Switch, SPST-NO, Off-Mom, 0.01 A, 32 VDC, SMD; Manufacturer: C&K Components; CurrentRating_mA: 10A; PositionCount: 1; SizeX_mm: 4.6; SizeY_mm: 2.8; SizeZ_mm: 1.9; SizeArea_mm2: 12.88; VDC_V: 32V; SizeAreaWB_mm2: 21.28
